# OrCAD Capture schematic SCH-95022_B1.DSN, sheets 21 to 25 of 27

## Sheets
21 Page27 WIFI/BT: size B
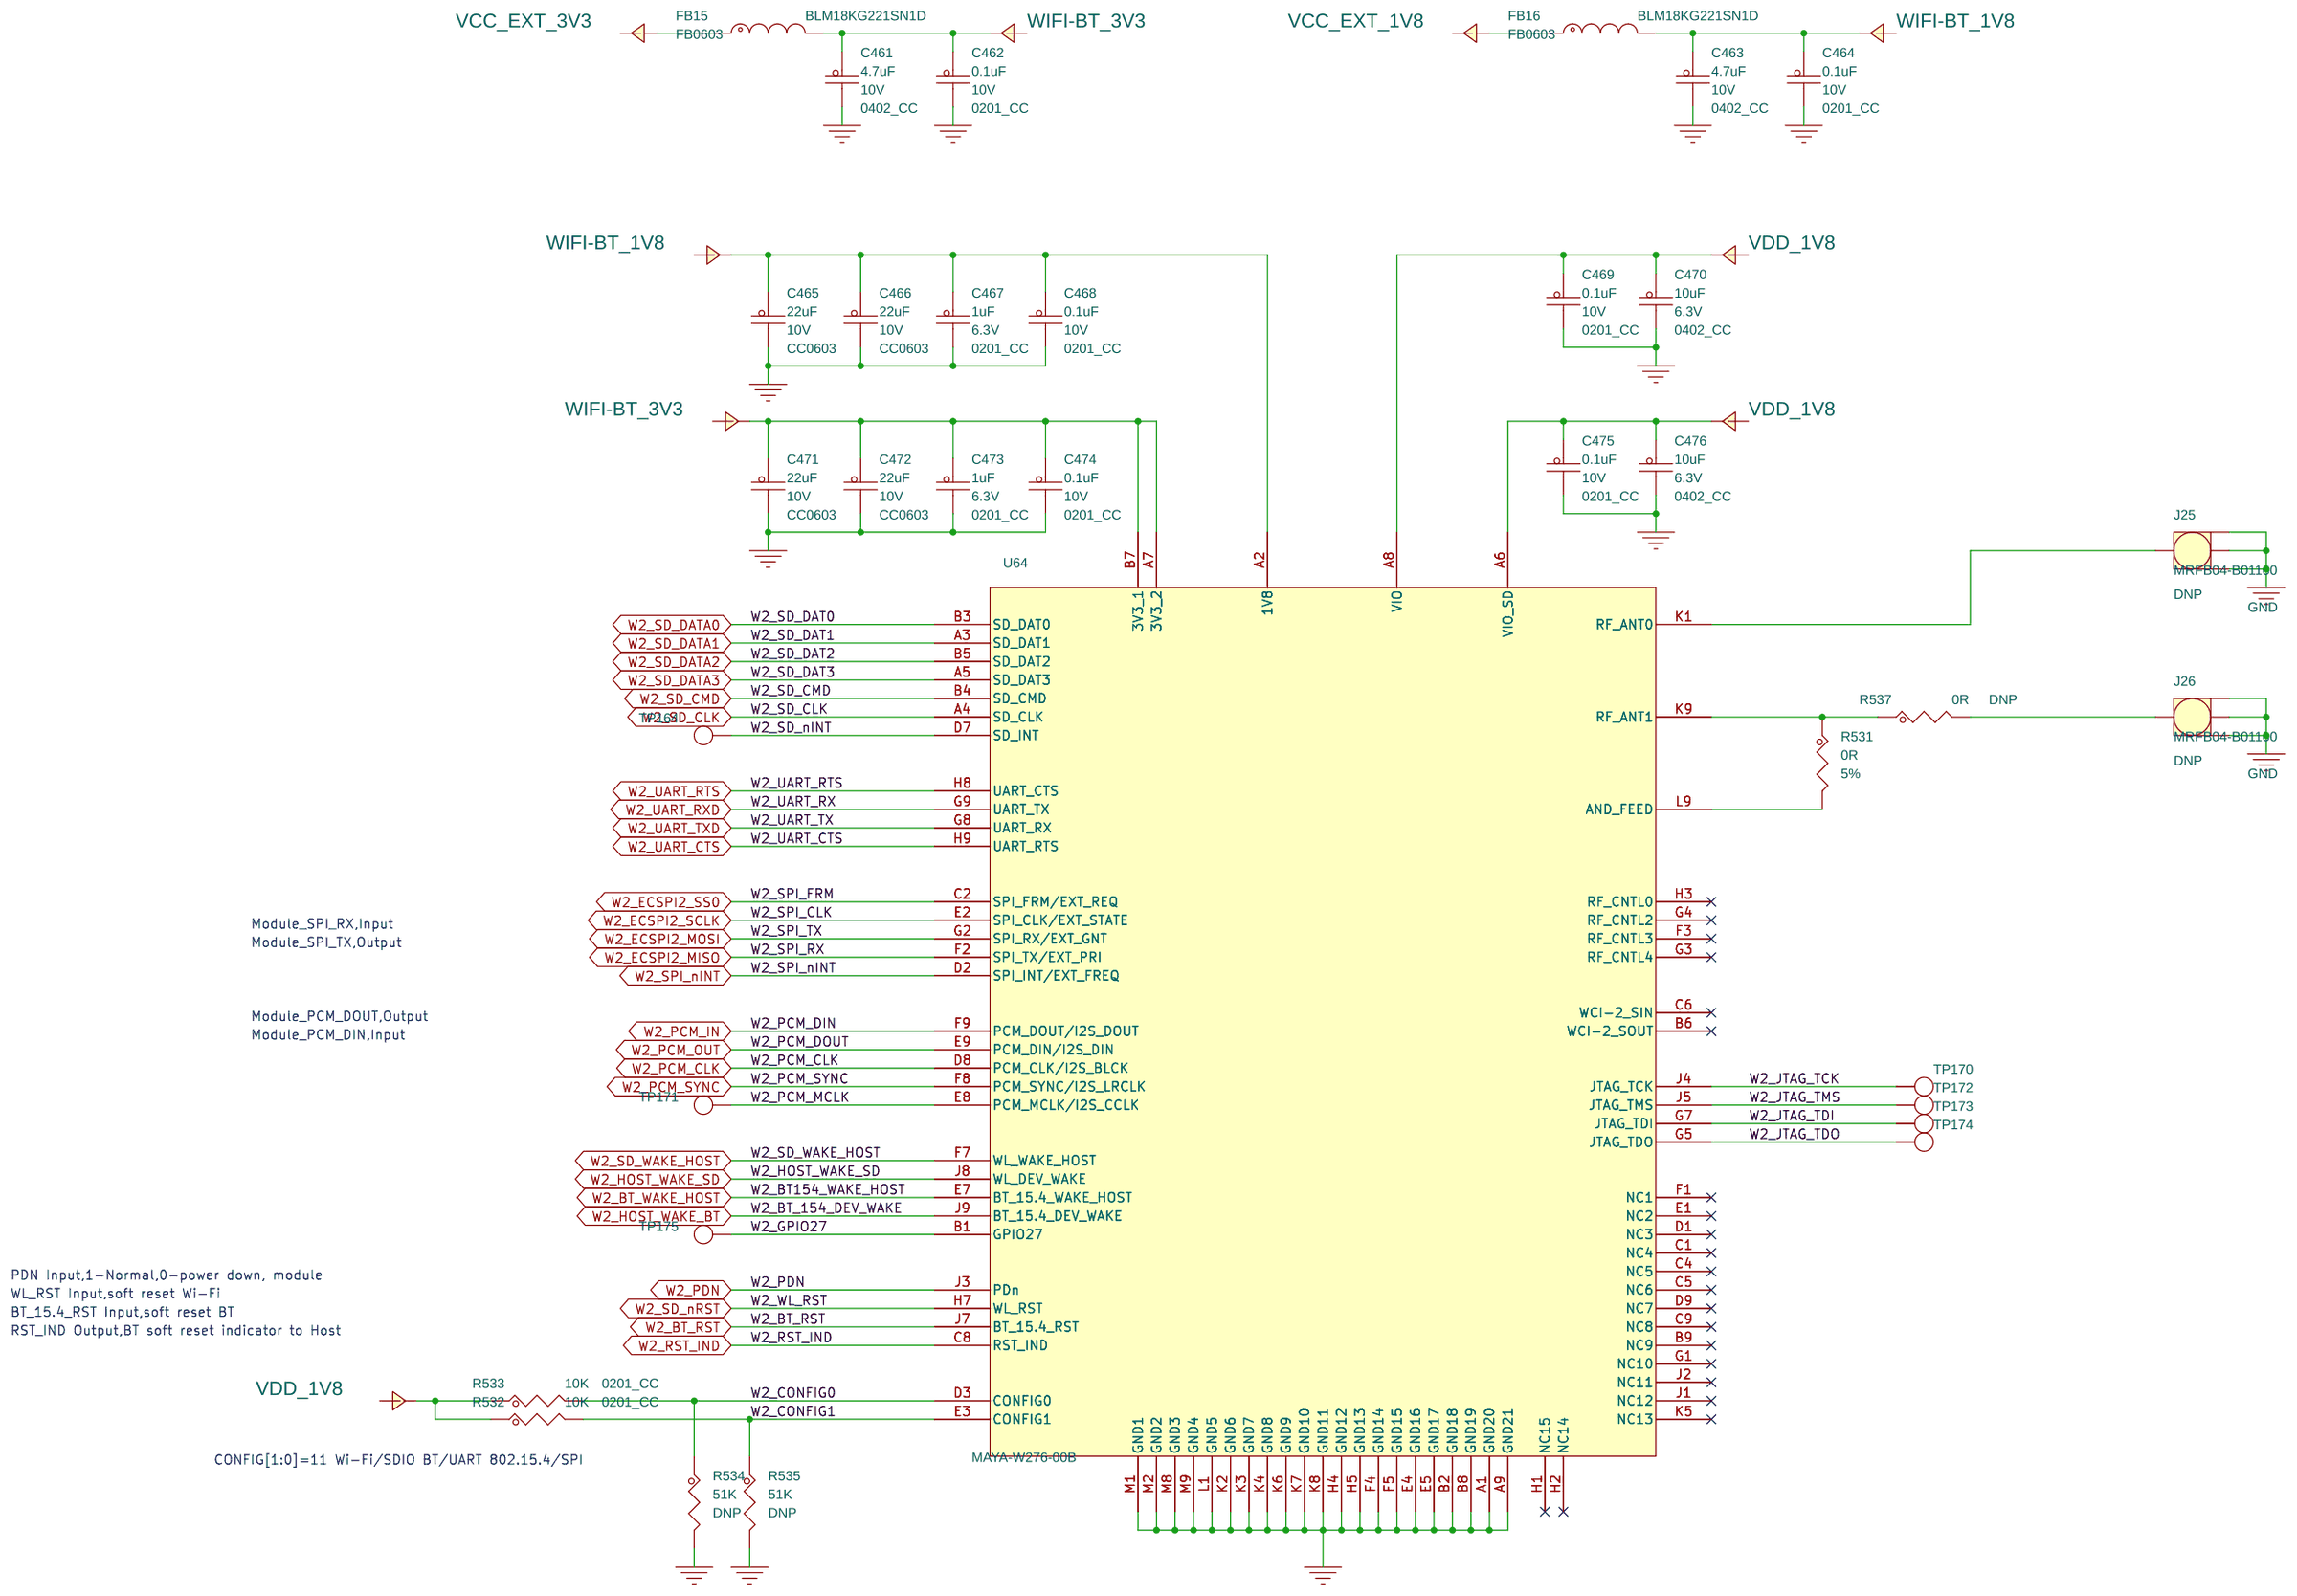
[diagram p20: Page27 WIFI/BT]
22 Page09 eMMC/QSPI: size B
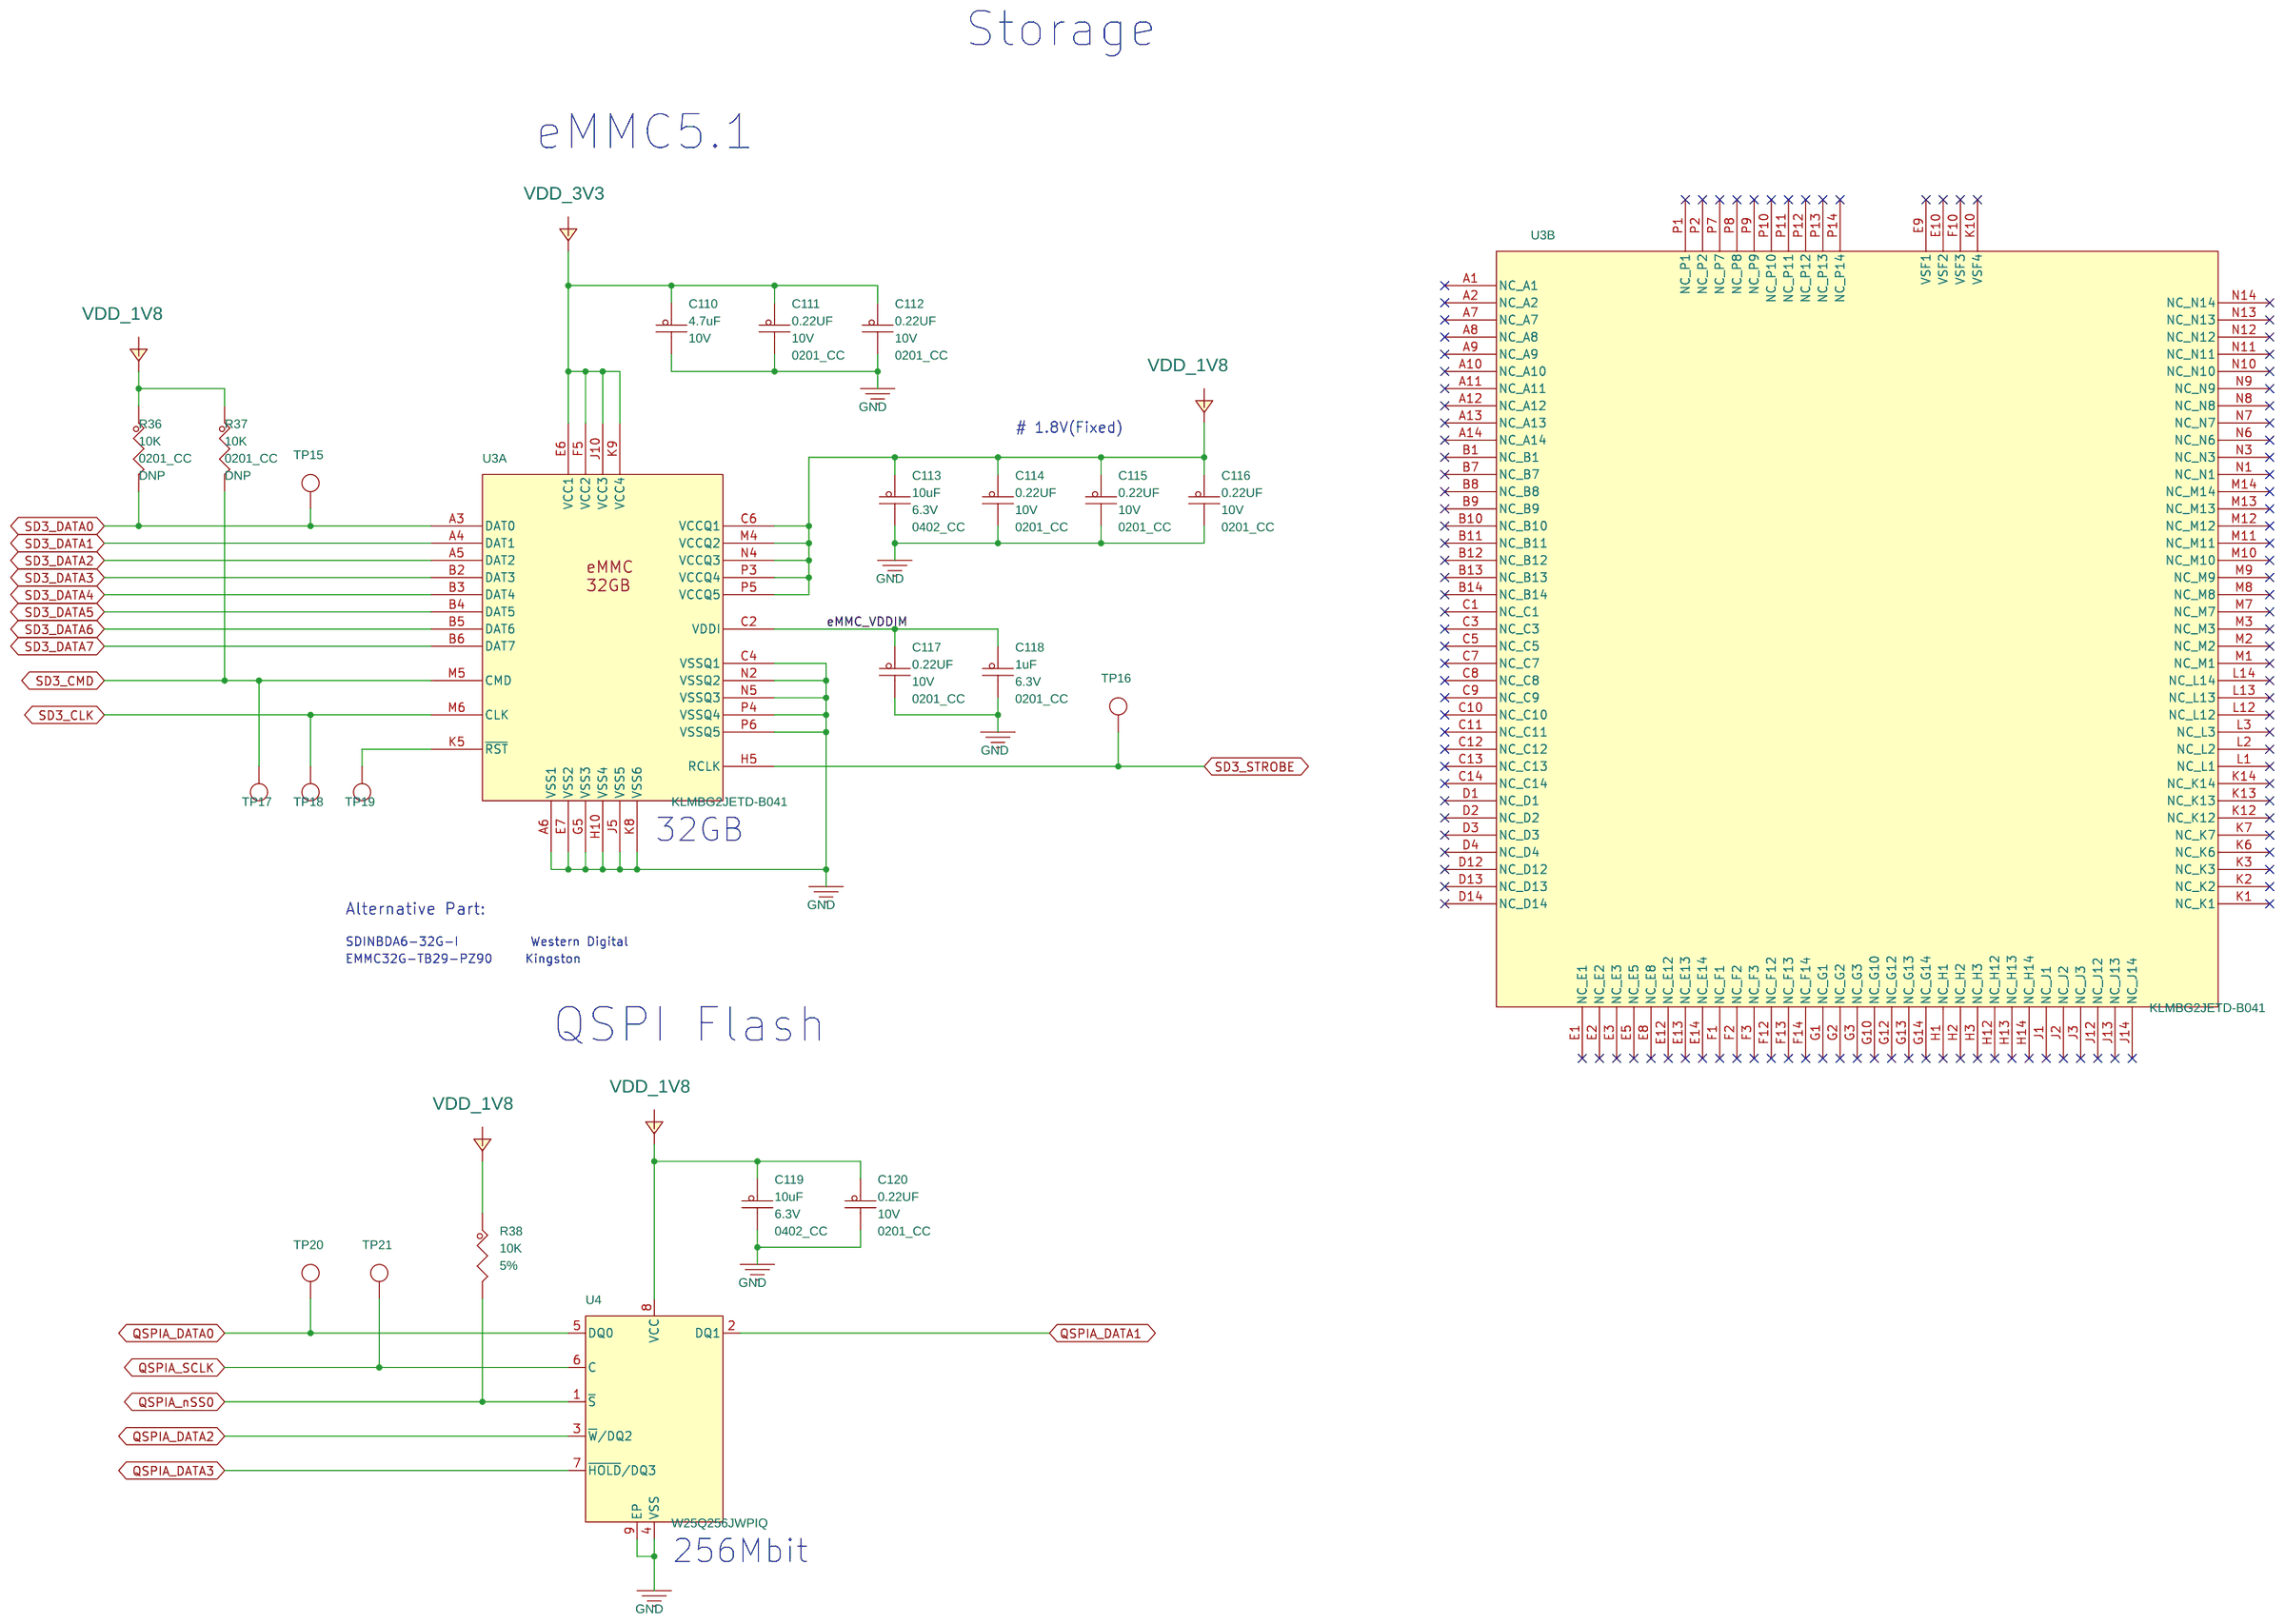
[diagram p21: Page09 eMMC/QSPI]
23 Page26 M.2 KEY-E WIFI/BT: size A3
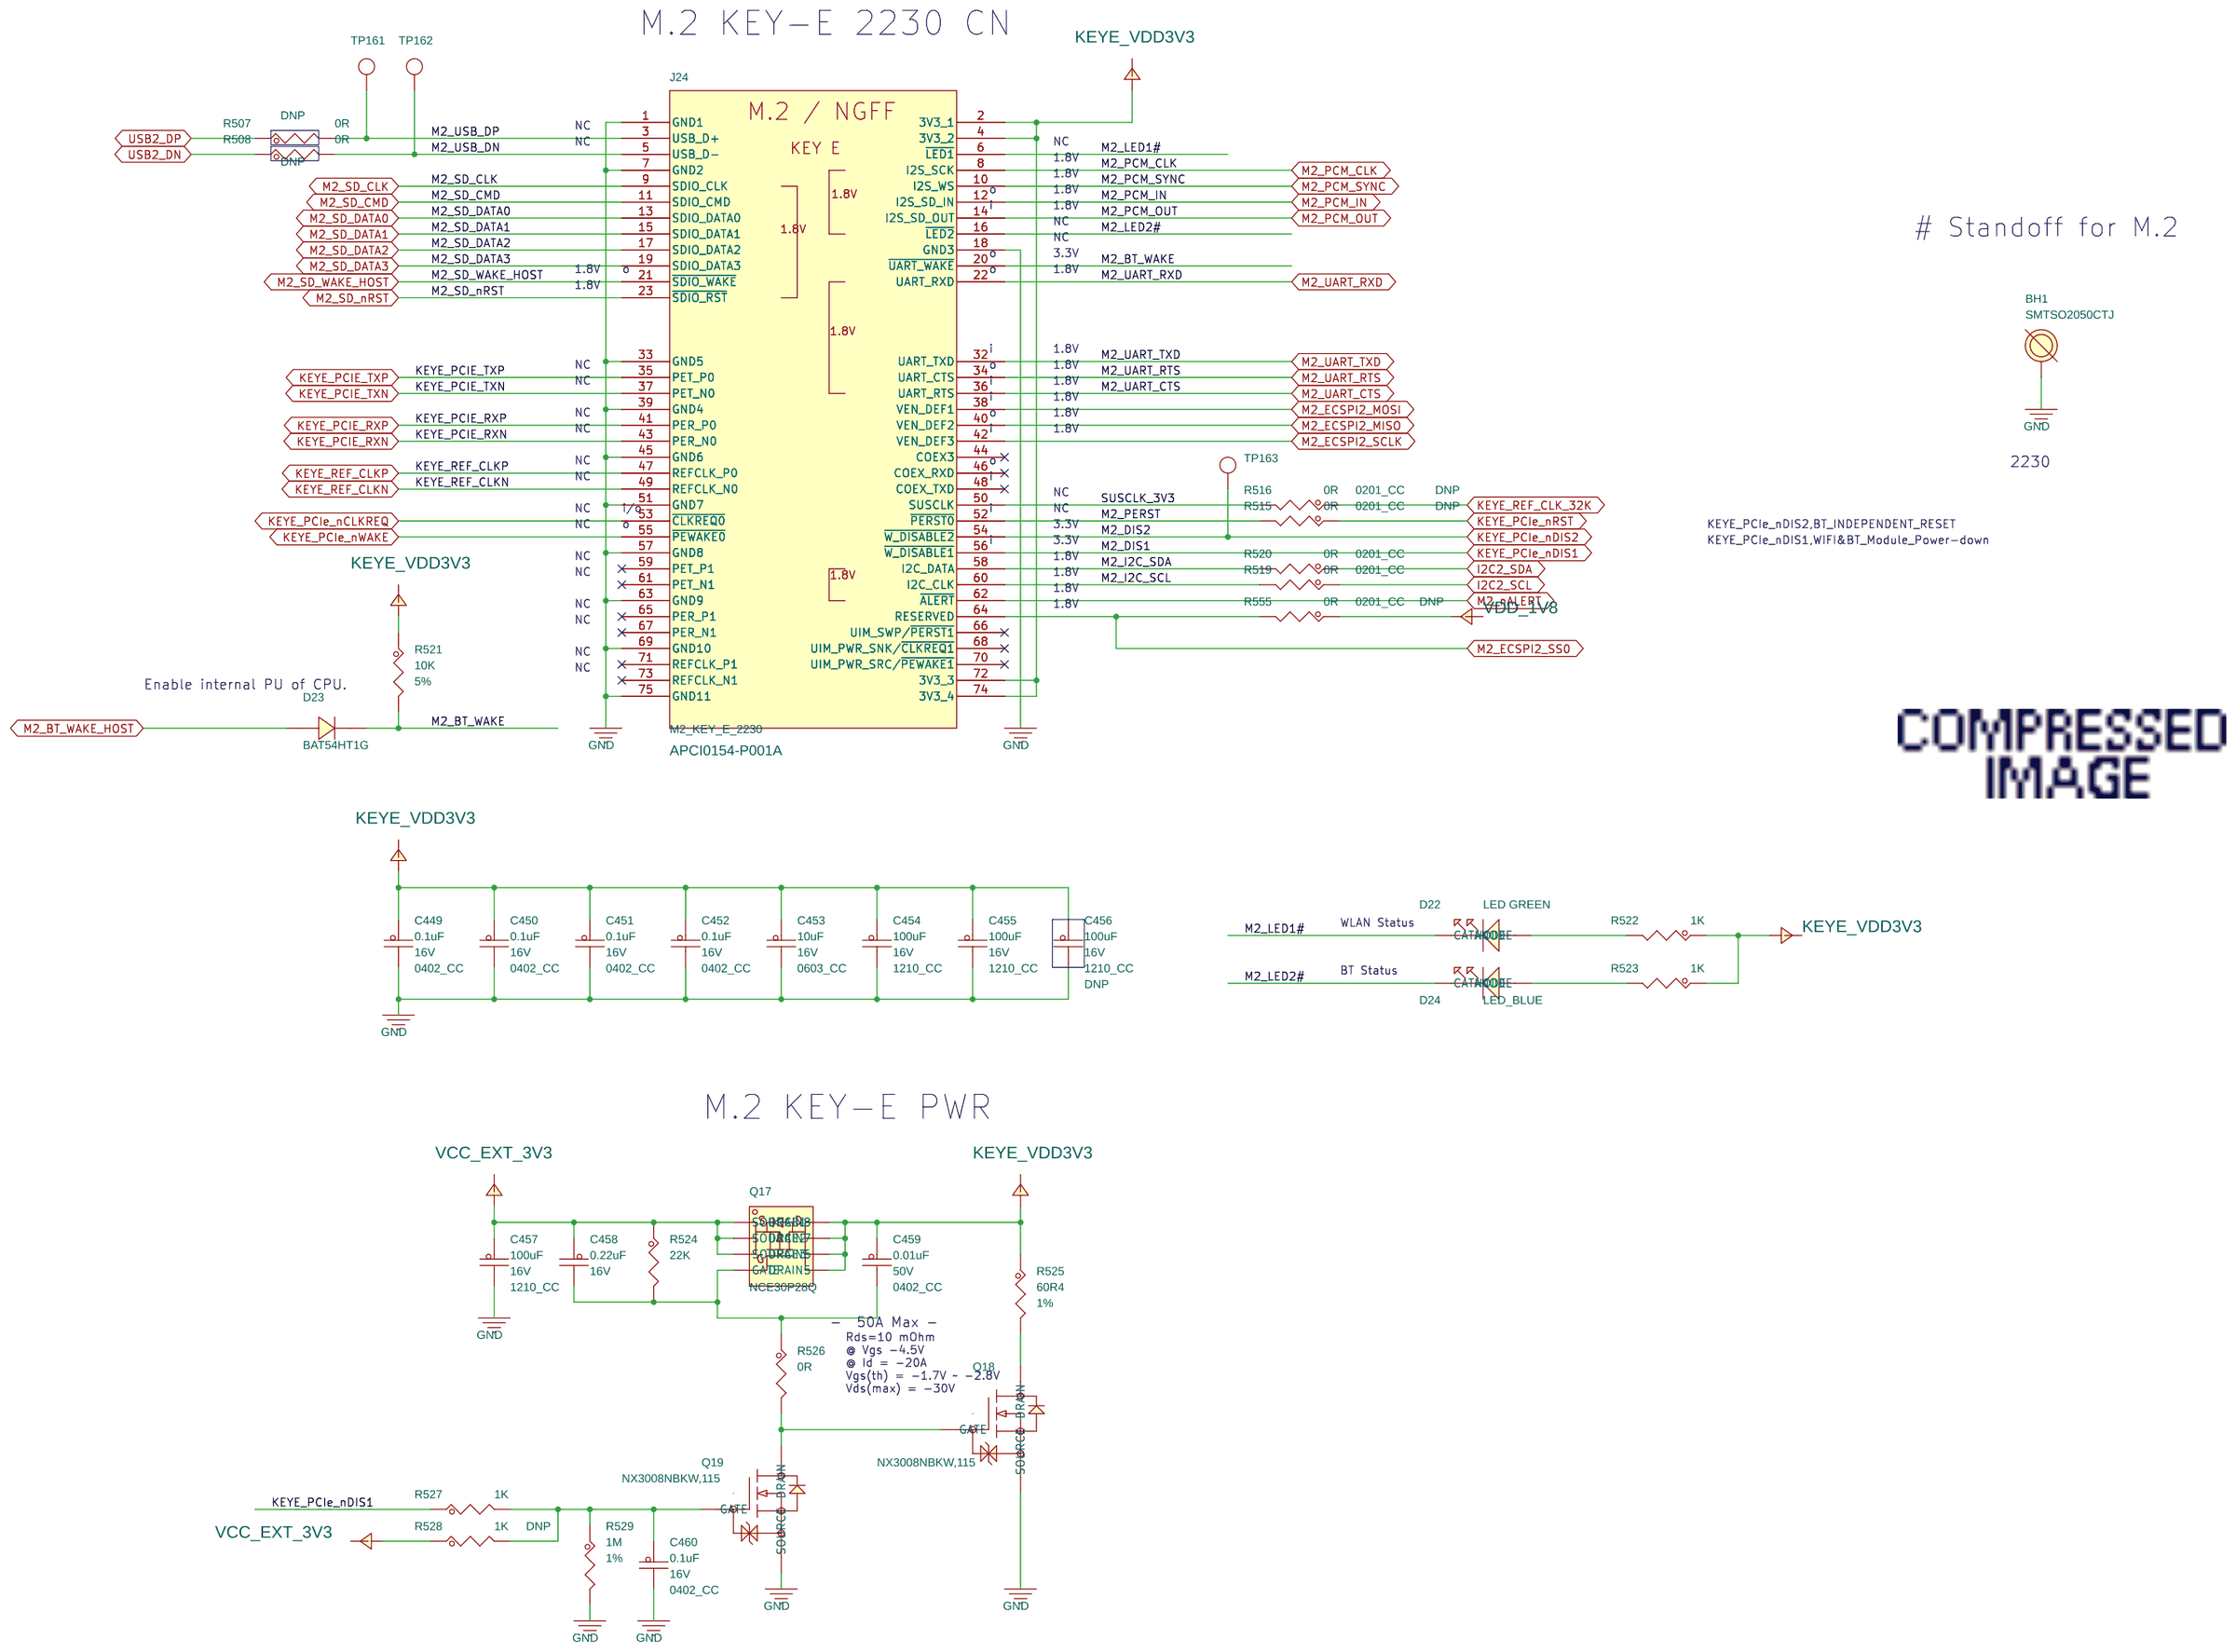
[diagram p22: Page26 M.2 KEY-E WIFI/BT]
24 Page22 DEBUG/JTAG/CAN/RTC: size C
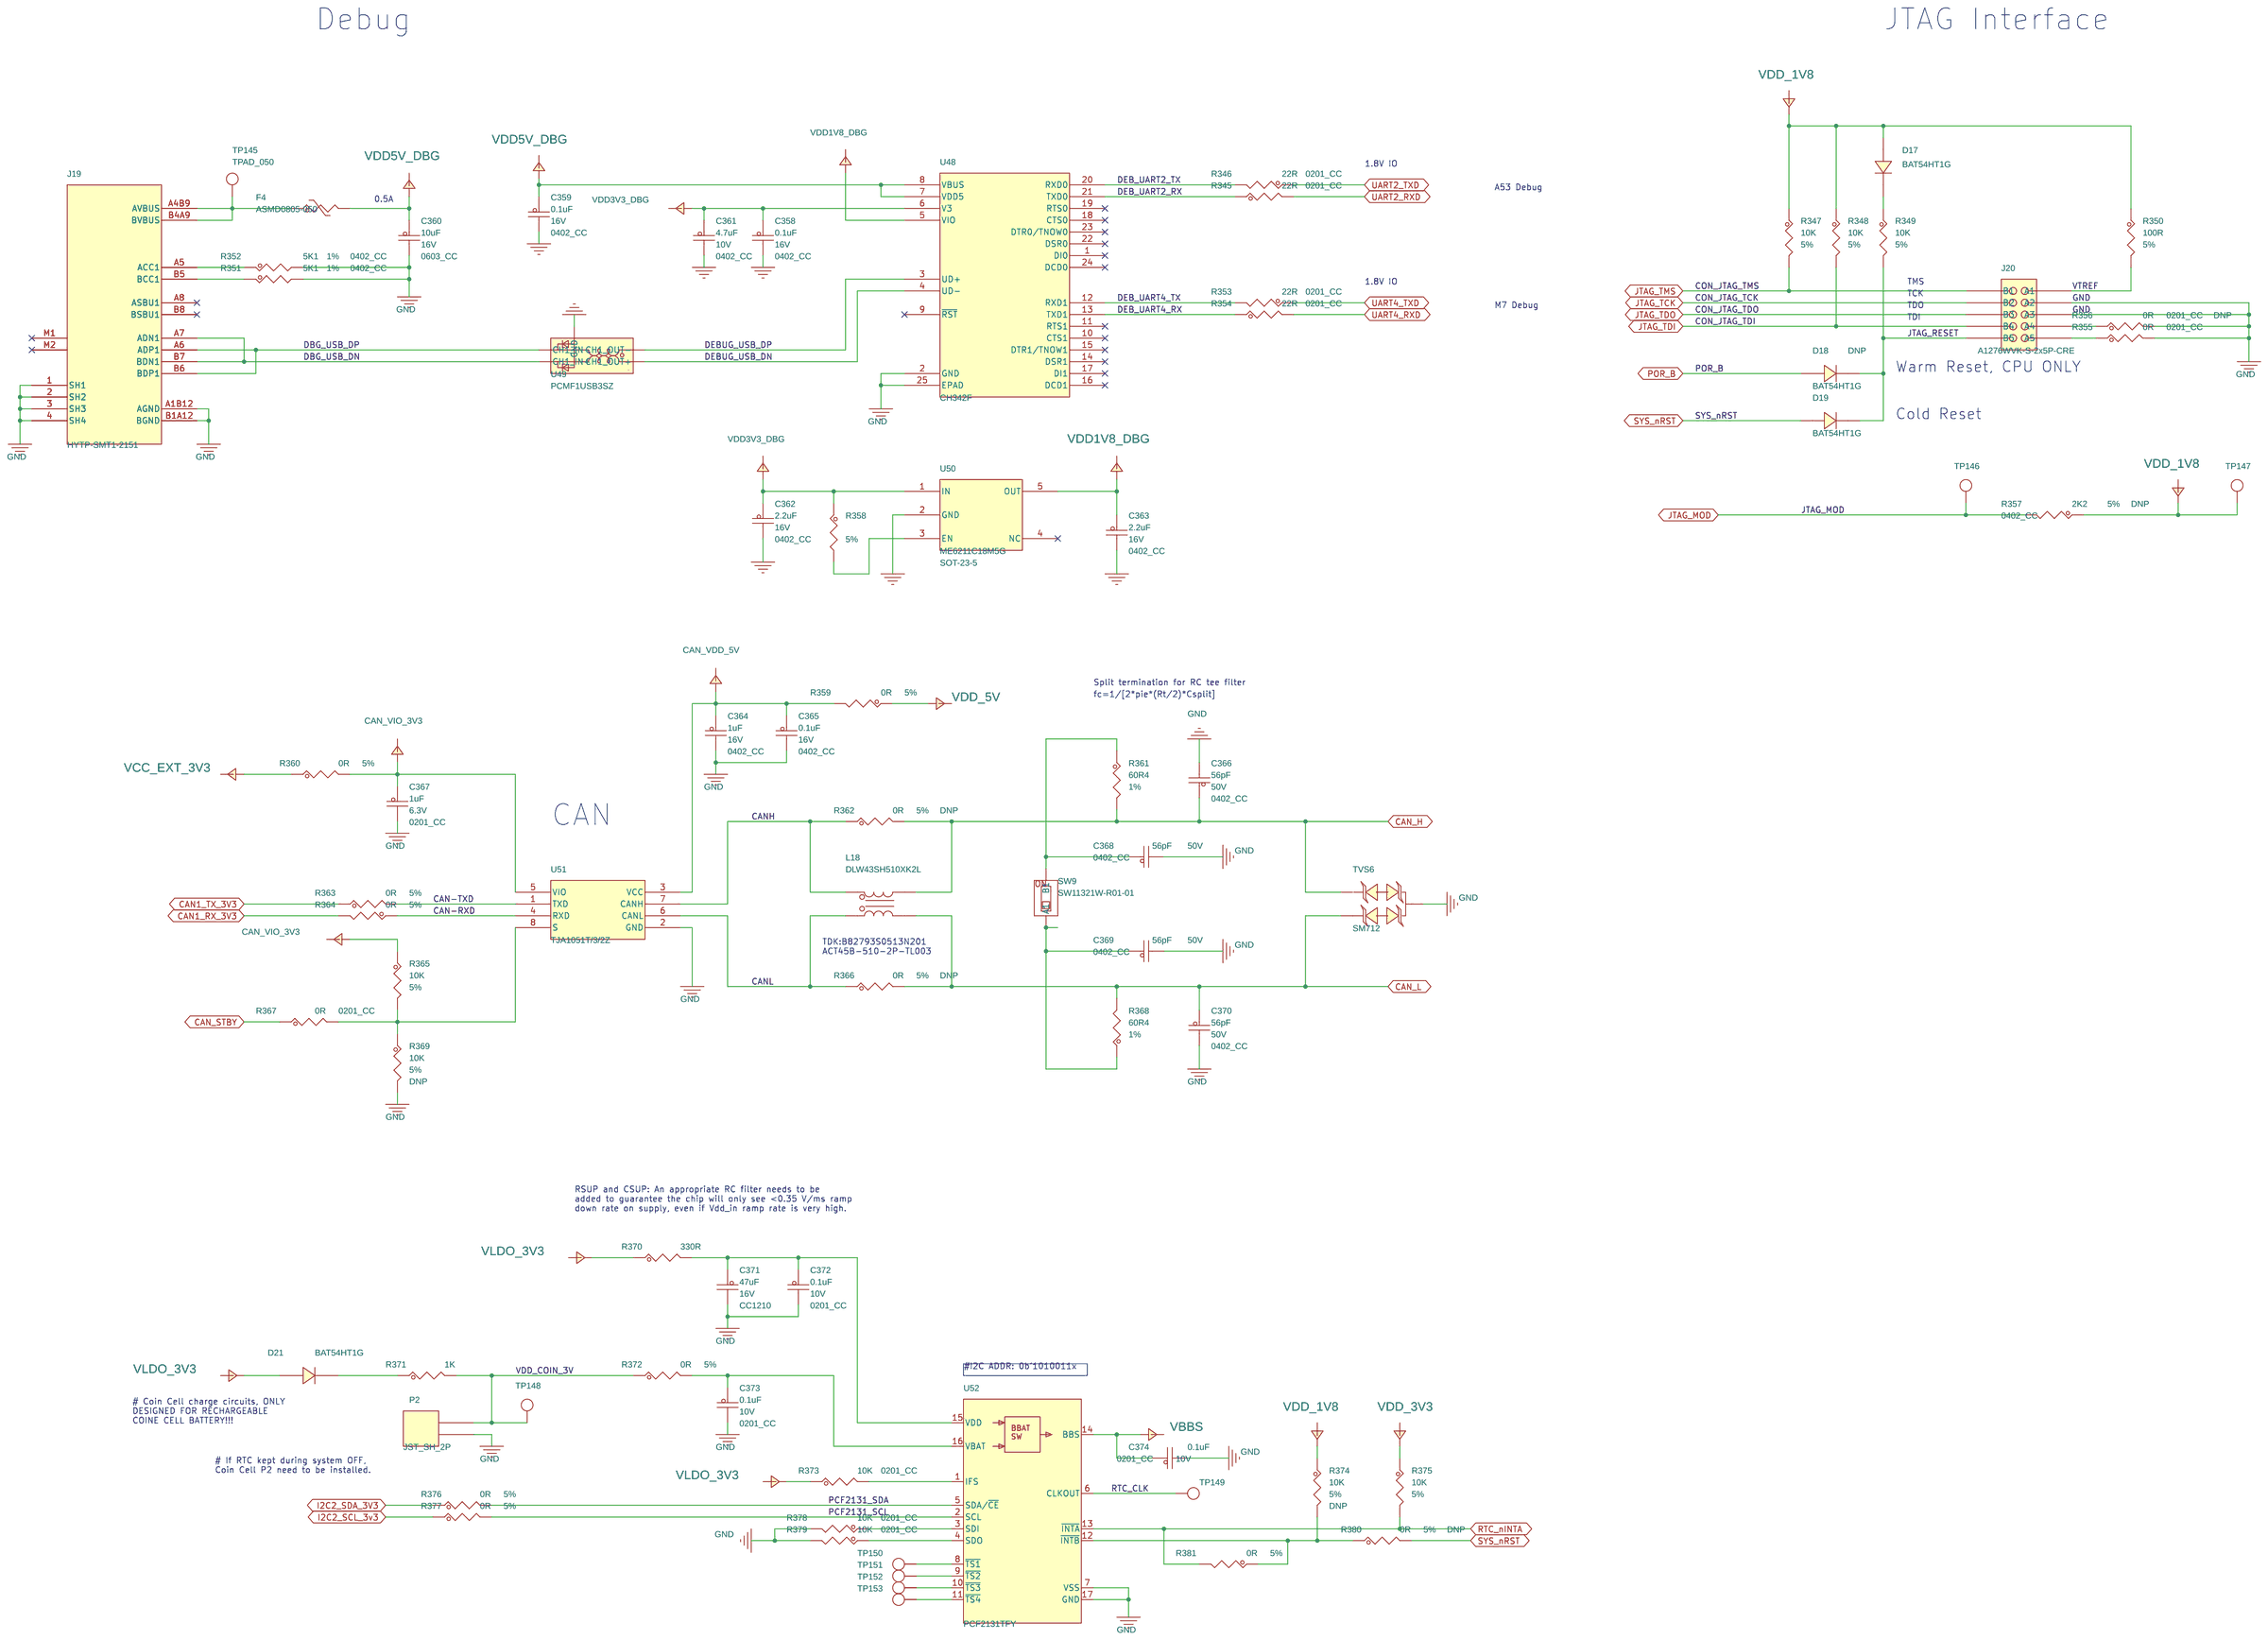
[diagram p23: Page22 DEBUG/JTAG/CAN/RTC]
25 Page19 MIPI CSI1/CSI2/DSI: size B
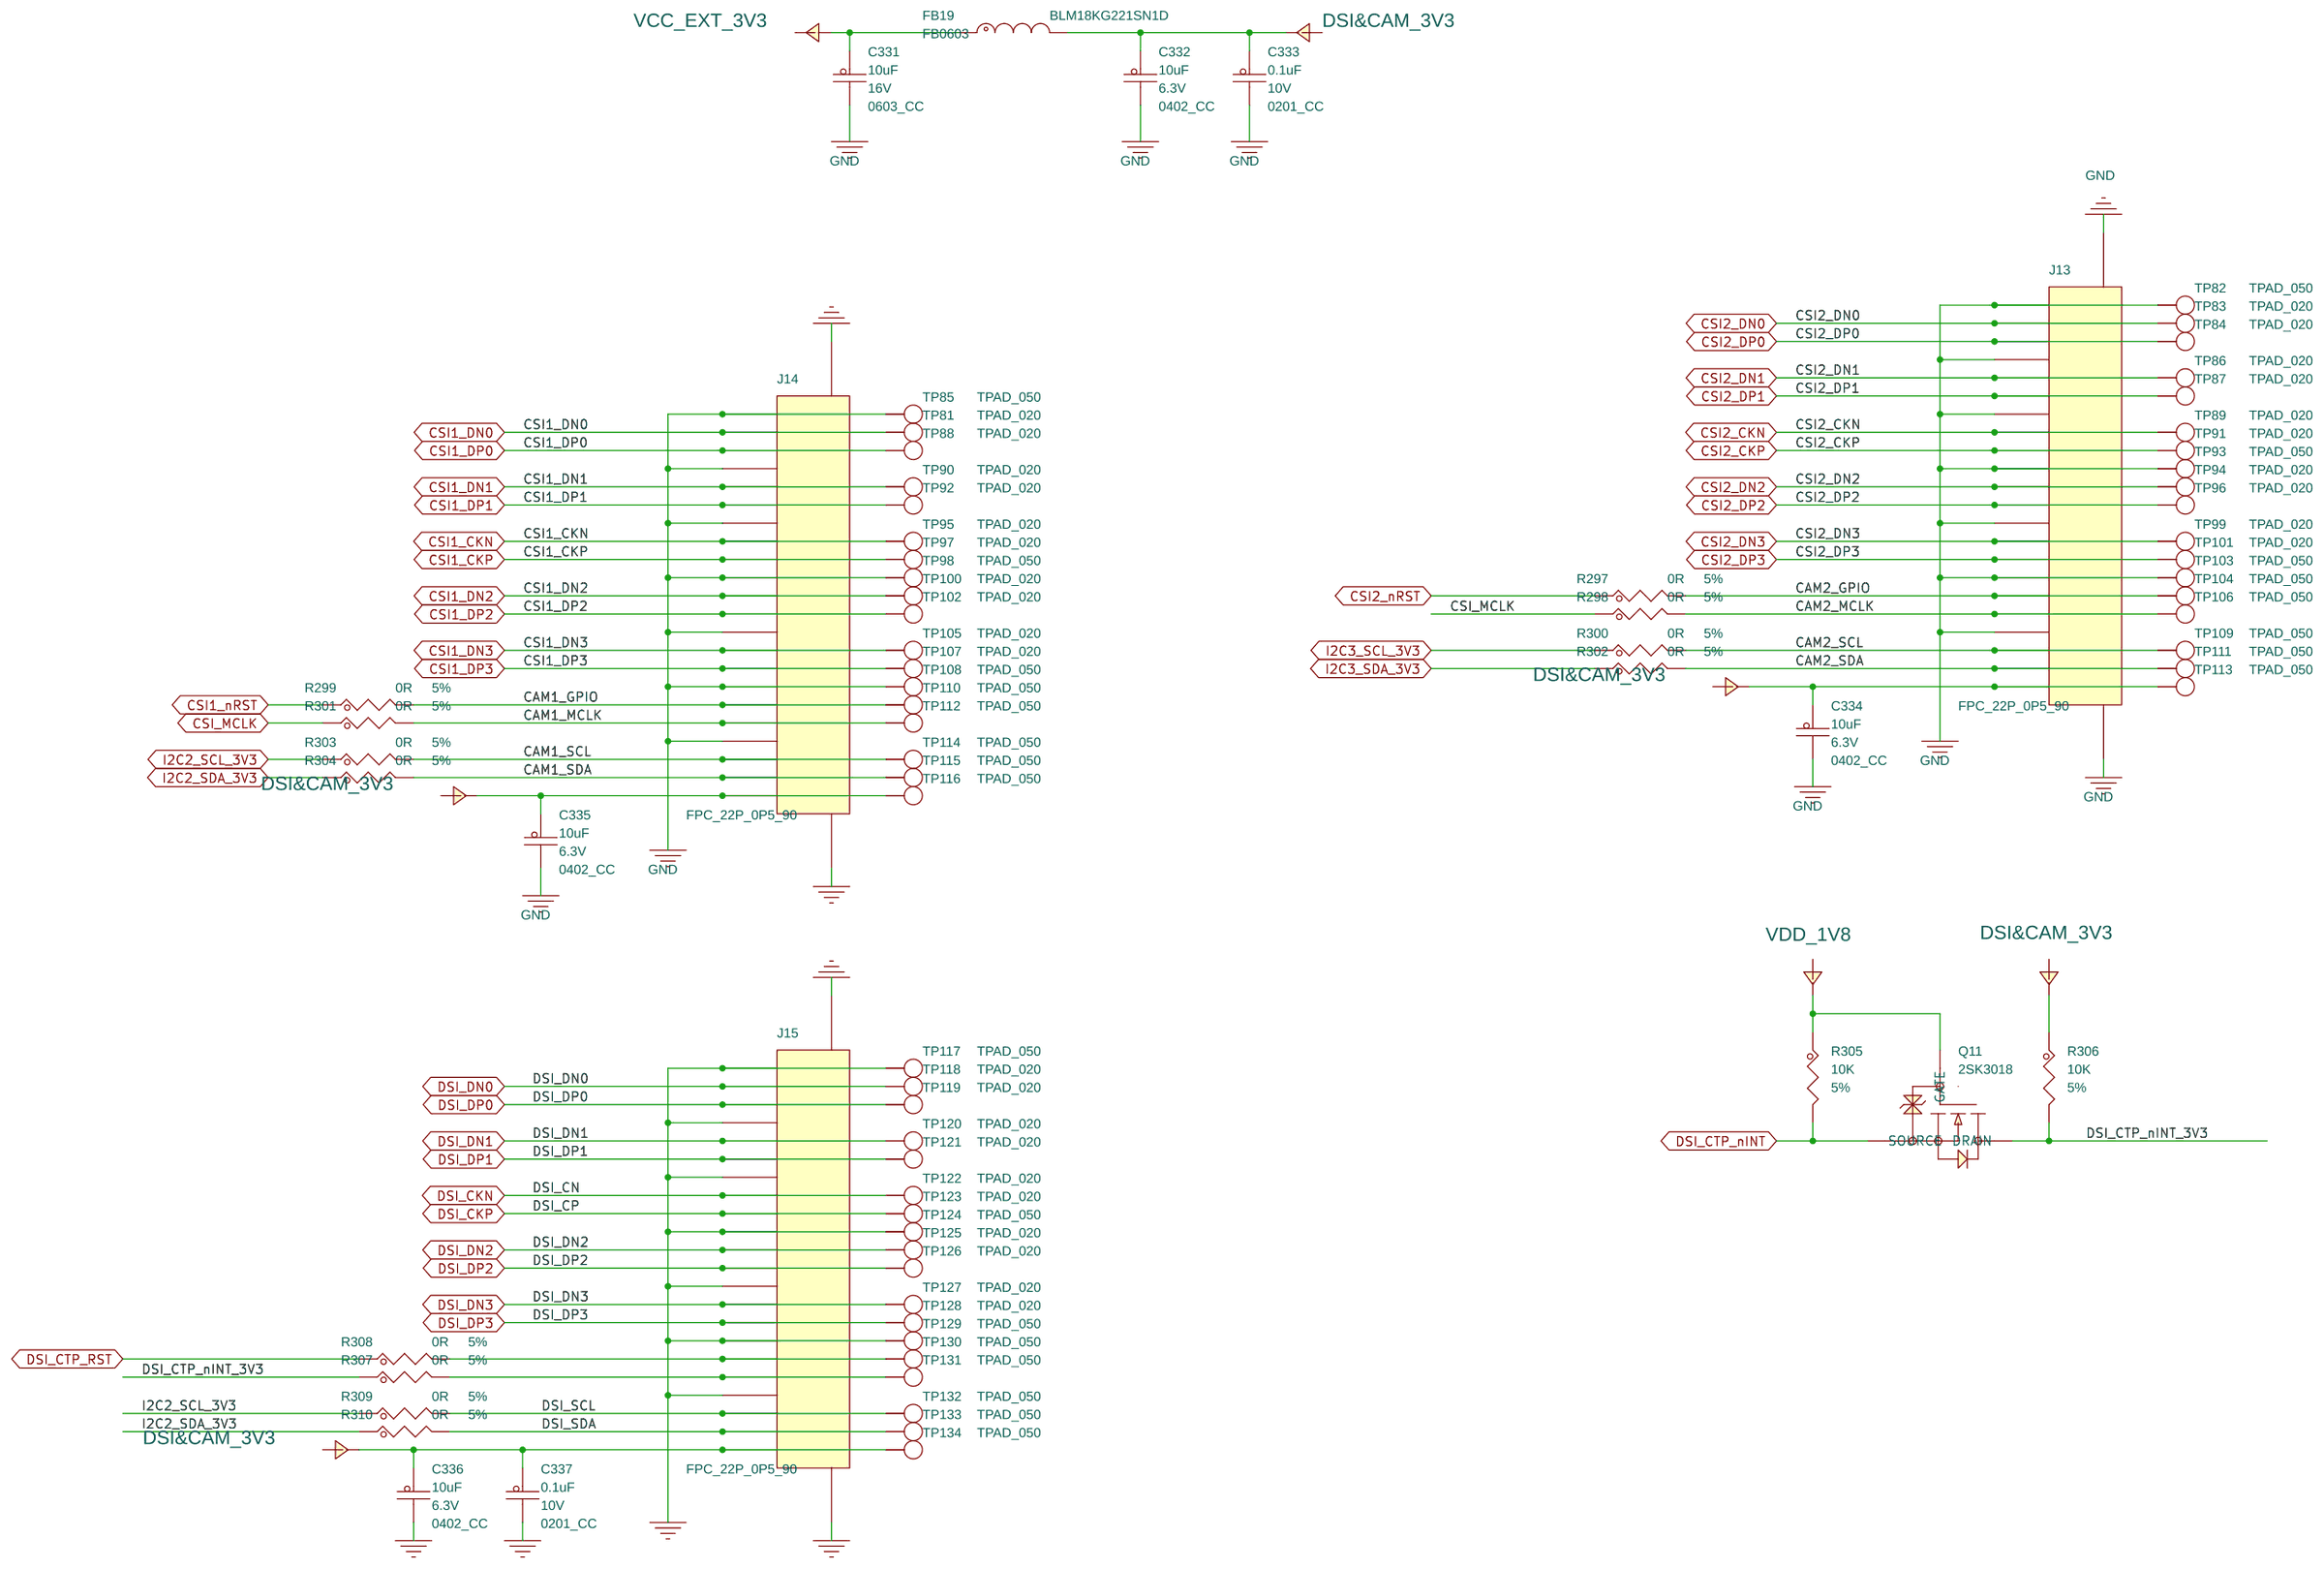
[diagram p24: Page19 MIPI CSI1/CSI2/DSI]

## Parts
sheet Page09 eMMC/QSPI
C110  4.7uF  [0402_CC]
C111  0.22UF  [0201_CC]
C112  0.22UF  [0201_CC]
C113  10uF  [0402_CC]
C114  0.22UF  [0201_CC]
C115  0.22UF  [0201_CC]
C116  0.22UF  [0201_CC]
C117  0.22UF  [0201_CC]
C118  1uF  [0201_CC]
C119  10uF  [0402_CC]
C120  0.22UF  [0201_CC]
R36  10K  [0201_CC]
R37  10K  [0201_CC]
R38  10K  [0402_CC]
TP15  TPAD_020  [tpad_020]
TP16  TPAD_020  [tpad_020]
TP17  TPAD_020  [tpad_020]
TP18  TPAD_020  [tpad_020]
TP19  TPAD_015  [TPAD_015]
TP20  TPAD_015  [TPAD_015]
TP21  TPAD_015  [TPAD_015]
U3  KLMBG2JETD-B041  [fbga153_0p5_11p5x13]  (sections A,B)
U4  W25Q256JWPIQ  [dfn8_1p27_6x5mm_3p1]
sheet Page19 MIPI CSI1/CSI2/DSI
C331  10uF  [0603_CC]
C332  10uF  [0402_CC]
C333  0.1uF  [0201_CC]
C334  10uF  [0402_CC]
C335  10uF  [0402_CC]
C336  10uF  [0402_CC]
C337  0.1uF  [0201_CC]
FB19  BLM18KG221SN1D  [FB0603]
J13  FPC_22P_0P5_90  [FPC_22P_0P5_90]
J14  FPC_22P_0P5_90  [FPC_22P_0P5_90]
J15  FPC_22P_0P5_90  [FPC_22P_0P5_90]
Q11  2SK3018  [SOT_323]
R297  0R  [0402_CC]
R298  0R  [0402_CC]
R299  0R  [0402_CC]
R300  0R  [0402_CC]
R301  0R  [0402_CC]
R302  0R  [0402_CC]
R303  0R  [0402_CC]
R304  0R  [0402_CC]
R305  10K  [0402_CC]
R306  10K  [0402_CC]
R307  0R  [0402_CC]
R308  0R  [0402_CC]
R309  0R  [0402_CC]
R310  0R  [0402_CC]
TP81  TPAD_020  [TPAD_020]
TP82  TPAD_050  [TPAD_050]
TP83  TPAD_020  [TPAD_020]
TP84  TPAD_020  [TPAD_020]
TP85  TPAD_050  [TPAD_050]
TP86  TPAD_020  [TPAD_020]
TP87  TPAD_020  [TPAD_020]
TP88  TPAD_020  [TPAD_020]
TP89  TPAD_020  [TPAD_020]
TP90  TPAD_020  [TPAD_020]
TP91  TPAD_020  [TPAD_020]
TP92  TPAD_020  [TPAD_020]
TP93  TPAD_050  [TPAD_050]
TP94  TPAD_020  [TPAD_020]
TP95  TPAD_020  [TPAD_020]
TP96  TPAD_020  [TPAD_020]
TP97  TPAD_020  [TPAD_020]
TP98  TPAD_050  [TPAD_050]
TP99  TPAD_020  [TPAD_020]
TP100  TPAD_020  [TPAD_020]
TP101  TPAD_020  [TPAD_020]
TP102  TPAD_020  [TPAD_020]
TP103  TPAD_050  [TPAD_050]
TP104  TPAD_050  [TPAD_050]
TP105  TPAD_020  [TPAD_020]
TP106  TPAD_050  [TPAD_050]
TP107  TPAD_020  [TPAD_020]
TP108  TPAD_050  [TPAD_050]
TP109  TPAD_050  [TPAD_050]
TP110  TPAD_050  [TPAD_050]
TP111  TPAD_050  [TPAD_050]
TP112  TPAD_050  [TPAD_050]
TP113  TPAD_050  [TPAD_050]
TP114  TPAD_050  [TPAD_050]
TP115  TPAD_050  [TPAD_050]
TP116  TPAD_050  [TPAD_050]
TP117  TPAD_050  [TPAD_050]
TP118  TPAD_020  [TPAD_020]
TP119  TPAD_020  [TPAD_020]
TP120  TPAD_020  [TPAD_020]
TP121  TPAD_020  [TPAD_020]
TP122  TPAD_020  [TPAD_020]
TP123  TPAD_020  [TPAD_020]
TP124  TPAD_050  [TPAD_050]
TP125  TPAD_020  [TPAD_020]
TP126  TPAD_020  [TPAD_020]
TP127  TPAD_020  [TPAD_020]
TP128  TPAD_020  [TPAD_020]
TP129  TPAD_050  [TPAD_050]
TP130  TPAD_050  [TPAD_050]
TP131  TPAD_050  [TPAD_050]
TP132  TPAD_050  [TPAD_050]
TP133  TPAD_050  [TPAD_050]
TP134  TPAD_050  [TPAD_050]
sheet Page22 DEBUG/JTAG/CAN/RTC
C358  0.1uF  [0402_CC]
C359  0.1uF  [0402_CC]
C360  10uF  [0603_CC]
C361  4.7uF  [0402_CC]
C362  2.2uF  [0402_CC]
C363  2.2uF  [0402_CC]
C364  1uF  [0402_CC]
C365  0.1uF  [0402_CC]
C366  56pF  [0402_CC]
C367  1uF  [0201_CC]
C368  56pF  [0402_CC]
C369  56pF  [0402_CC]
C370  56pF  [0402_CC]
C371  47uF  [CC1210]
C372  0.1uF  [0201_CC]
C373  0.1uF  [0201_CC]
C374  0.1uF  [0201_CC]
D17  BAT54HT1G  [SOD323]
D18  BAT54HT1G  [SOD323]
D19  BAT54HT1G  [SOD323]
D21  BAT54HT1G  [SOD323]
F4  ASMD0805-050  [R0805]
J19  HYTP-SMT1-2151  [TYPEC16P_8P94X7P30X3P16]
J20  A1276WVK-S-2x5P-CRE  [hdr205_10m_50_sm_k]
L18  DLW43SH510XK2L  [IND_DLW43]
P2  JST_SH_2P  [sh_2p]
R345  22R  [0201_CC]
R346  22R  [0201_CC]
R347  10K  [0402_CC]
R348  10K  [0402_CC]
R349  10K  [0402_CC]
R350  100R  [0402_CC]
R351  5K1  [0402_CC]
R352  5K1  [0402_CC]
R353  22R  [0201_CC]
R354  22R  [0201_CC]
R355  0R  [0201_CC]
R356  0R  [0201_CC]
R357  2K2  [0402_CC]
R358  100K  [0402_CC]
R359  0R  [0402_CC]
R360  0R  [0402_CC]
R361  60R4  [0603_CC]
R362  0R  [0402_CC]
R363  0R  [0402_CC]
R364  0R  [0402_CC]
R365  10K  [0402_CC]
R366  0R  [0402_CC]
R367  0R  [0201_CC]
R368  60R4  [0603_CC]
R369  10K  [0402_CC]
R370  330R  [0402_CC]
R371  1K  [0402_CC]
R372  0R  [0402_CC]
R373  10K  [0201_CC]
R374  10K  [0402_CC]
R375  10K  [0402_CC]
R376  0R  [0402_CC]
R377  0R  [0402_CC]
R378  10K  [0201_CC]
R379  10K  [0201_CC]
R380  0R  [0402_CC]
R381  0R  [0402_CC]
SW9  SW11321W-R01-01  [SW_1P27_1P]
TP145  TPAD_050  [TPAD_050]
TP146  TPAD_050  [TPAD_050]
TP147  TPAD_050  [TPAD_050]
TP148  TPAD_020  [tpad_020]
TP149  TPAD_015  [TPAD_015]
TP150  TPAD_015  [TPAD_015]
TP151  TPAD_015  [TPAD_015]
TP152  TPAD_015  [TPAD_015]
TP153  TPAD_015  [TPAD_015]
TVS6  SM712  [SOT-23]
U48  CH342F  [QFN24P_0_5]
U49  PCMF1USB3SZ  [wlcsp5_0p4_0p82x1p22]
U50  ME6211C18M5G  [SOT-23-5]
U51  TJA1051T/3/2Z  [SOP8]
U52  PCF2131TFY  [so16_0p5_3p5x4p5_mm]
sheet Page26 M.2 KEY-E WIFI/BT
BH1  SMTSO2050CTJ  [PTH_3R73x6R20]
C449  0.1uF  [0402_CC]
C450  0.1uF  [0402_CC]
C451  0.1uF  [0402_CC]
C452  0.1uF  [0402_CC]
C453  10uF  [0603_CC]
C454  100uF  [1210_CC]
C455  100uF  [1210_CC]
C456  100uF  [1210_CC]
C457  100uF  [1210_CC]
C458  0.22uF  [0402_CC]
C459  0.01uF  [0402_CC]
C460  0.1uF  [0402_CC]
D22  LED GREEN  [LED_0603]
D23  BAT54HT1G  [SOD323]
D24  LED_BLUE  [led_0603_11mil]
J24  M2_KEY_E_2230  [con_75_0p5_22x9_ra1]
Q17  NCE30P28Q  [DFN_3x3-8L]
Q18  NX3008NBKW,115  [sc70_3]
Q19  NX3008NBKW,115  [sc70_3]
R507  0R  [0402_CC]
R508  0R  [0402_CC]
R515  0R  [0201_CC]
R516  0R  [0201_CC]
R519  0R  [0201_CC]
R520  0R  [0201_CC]
R521  10K  [0402_CC]
R522  1K  [0402_CC]
R523  1K  [0402_CC]
R524  22K  [0402_CC]
R525  60R4  [0603_CC]
R526  0R  [0402_CC]
R527  1K  [0402_CC]
R528  1K  [0402_CC]
R529  1M  [0402_CC]
R555  0R  [0201_CC]
TP161  TPAD_020  [tpad_020]
TP162  TPAD_020  [tpad_020]
TP163  TPAD_020  [tpad_020]
sheet Page27 WIFI/BT
C461  4.7uF  [0402_CC]
C462  0.1uF  [0201_CC]
C463  4.7uF  [0402_CC]
C464  0.1uF  [0201_CC]
C465  22uF  [CC0603]
C466  22uF  [CC0603]
C467  1uF  [0201_CC]
C468  0.1uF  [0201_CC]
C469  0.1uF  [0201_CC]
C470  10uF  [0402_CC]
C471  22uF  [CC0603]
C472  22uF  [CC0603]
C473  1uF  [0201_CC]
C474  0.1uF  [0201_CC]
C475  0.1uF  [0201_CC]
C476  10uF  [0402_CC]
FB15  BLM18KG221SN1D  [FB0603]
FB16  BLM18KG221SN1D  [FB0603]
J25  MRFB04-B01100  [IPEX_4]
J26  MRFB04-B01100  [IPEX_4]
R531  0R  [0402_CC]
R532  10K  [0201_CC]
R533  10K  [0201_CC]
R534  51K  [0402_CC]
R535  51K  [0402_CC]
R537  0R  [0402_CC]
TP164  TPAD_015  [TPAD_015]
TP170  TPAD_015  [TPAD_015]
TP171  TPAD_015  [TPAD_015]
TP172  TPAD_015  [TPAD_015]
TP173  TPAD_015  [TPAD_015]
TP174  TPAD_015  [TPAD_015]
TP175  TPAD_015  [TPAD_015]
U64  MAYA-W276-00B  [MAYA-W2]

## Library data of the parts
C110 C361 C461 C463 = CAP_NP: CAP CER 4.7uF 10V 10% X5R 0402; CAD_APPROVED: Yes; HEIGHT: 0.95MM; MFG_NAME01: SAMSUNG; MFG_PN01: CL05A475KP5NRNC; Polyhex_Number: PD.005.0058; ROHS: Yes; Temp Range: -55°C to + 85°C; Tolerance: 10%; VOLTAGE: 10V
C111 C112 C114-C117 C120 = CAP_NP: CAP CER 0.22UF 10V 20% X5R 0201; AGILE_PN: 150-78815; CAD_APPROVED: Yes; FPLIST: CC0201,CC0201_HD,0201_CC; HEIGHT: 0.33MM; MFG_NAME01: SAMSUNG; MFG_PN01: CL03A224KP3NNNH; Polyhex_Number: PD.005.0029; ROHS: Yes; Tolerance: 20%; VOLTAGE: 10V
C113 C119 C332 C334-C336 C470 C476 = CAP_NP: CAP CER 10UF 6.3V 20% X5R 0402; AGILE_PN: 150-79163; CAD_APPROVED: Yes; FPLIST: CC0402_25,CC0402_HD,0402_CC; HEIGHT: 0.65 MM; MFG_NAME01: SAMSUNG; MFG_PN01: CL05A106MQ5NUNC; Polyhex_Number: PD.005.0031; ROHS: Yes; Tolerance: 20%; VOLTAGE: 6.3V
C118 C367 C467 C473 = CAP_NP: CAP CER 1uF 6.3V 10% X5R 0201; AGILE_PN: 150-79407; CAD_APPROVED: Yes; FPLIST: CC0201,CC0201_HD,0201_CC,0201_CC_012SM_NSP; HEIGHT: 0.35MM; MFG_NAME01: SAMSUNG; MFG_PN01: CL03A105KQ3CSNH; Package Size: 0201; Package Type: 7” reel; Polyhex_Number: PD.005.0030; ROHS: Yes; Tolerance: 10%; VOLTAGE: 6.3V
R36 R37 = RES: RES MF 10K 1/20W 5% 0201; ASSY_OPT: DNP; CAD_APPROVED: Yes; HEIGHT: 0.23mm; MFG_NAME01: YAGEO; MFG_PN01: RC0201JR-0710KL; Polyhex_Number: PD.004.0069; ROHS: Yes; Tolerance: 5%; VOLTAGE: 25V
R38 R305 R306 R347-R349 R365 R375 R521 = RES: RES MF 10K 1/16W 5% 0402; AGILE_PN: 470-75557; CAD_APPROVED: Yes; FPLIST: RC0402_25,RC0402_HD,0402_CC; HEIGHT: 0.4 MM; MFG_NAME01: YAGEO; MFG_PN01: RC0402JR-0710KL; Polyhex_Number: PD.004.0010; ROHS: Yes; Tolerance: 5%; VOLTAGE: 50V
TP15-TP18 TP81 TP83 TP84 TP86-TP92 TP94-TP97 TP99-TP102 TP105 TP107 TP118-TP123 TP125-TP128 TP148 TP161-TP163 = TESTLOOP: TEST POINT PAD 0.5MM DIA SMT, NO PART TO ORDER; AGILE_PN: 211-77484; ASSY_OPT: DNP; CAD_APPROVED: Yes; HEIGHT: 0.1MM; MFG_NAME01: NOT A COMPONENT; MFG_PN01: NOT A COMPONENT; Polyhex_Number: TEST POINT; ROHS: Yes
TP19-TP21 TP149-TP153 TP164 TP170-TP175 = TestLoop: TEST POINT PAD 15MIL DIA SMT, NO PART TO ORDER; AGILE_PN: 211-76645; ASSY_OPT: DNP; CAD_APPROVED: Yes; HEIGHT: 0.1MM; MFG_NAME01: NOT A COMPONENT; MFG_PN01: NOT A COMPONENT; Polyhex_Number: TEST POINT; ROHS: Yes
U3 = SDINBDG4-16G_VFBGA_153P: IC MEM NAND FLASH 32GB eMMC 5.1 CTLR 2.7-3.6V FBGA153; AGILE_PN: 342-00840; HEIGHT: 1MM; MFG_NAME01: SAMSUNG; Package Size: 11.5 mm x 13 mm x 1 mm; Polyhex_Number: PD.008.0032; ROHS: YES; Supply Voltage: 2.7 V to 3.6 V; Temp Range: -25°C to +85°C; VOLTAGE: 2.7-3.6V
U4 = MT25QL256ABA1EW9_9P: IC MEM FLASH SERIAL NOR 256MBIT; AGILE_PN: 334-77688; CAD_APPROVED: Yes; HEIGHT: 0.8 MM; MFG_NAME01: WINDOND; Polyhex_Number: PD.008.0338; ROHS: Yes; VOLTAGE: 1.7-2V
C331 C360 C453 = CAP_NP: CAP CER 10uF 16V 10% X5R 0603; CAD_APPROVED: Yes; HEIGHT: 0.55 MM; MFG_NAME01: SAMSUNG; MFG_PN01: CL10A106MO8NQN; Package Size: 0603; Polyhex_Number: PD.005.0001; ROHS: Yes; Tolerance: 10%; VOLTAGE: 16V
C333 C337 C372-C374 C462 C464 C468 C469 C474 C475 = CAP_NP: CAP CER 0.1uF 10V 20% X5R 0201; CAD_APPROVED: Yes; HEIGHT: 0.35MM; MFG_NAME01: SAMSUNG; MFG_PN01: CL03A104KP3NNNC; Package Size: 0201; Package Type: 7” reel; Polyhex_Number: PD.005.0054; ROHS: Yes; Tolerance: 20%; VOLTAGE: 10V
FB15 FB16 FB19 = Ferrite_Bead: FERRITE 0603 220Ohm@100MHz 2A; HEIGHT: 0.5mm; Irms: <Irms>; MFG_NAME01: Murata; Polyhex_Number: PD.009.0001; Temp Range: -55C to +125C; Temp_Range: -55C to +125C
J13-J15 = FPC_22P_0P5_90: CON FPC 22PIN 0.5mm Vertical Type; MFG_NAME01: WENZHANGJIMEI; MFG_PN01: 5001-FCZ0544-22R1-00; Polyhex_Number: PD.010.0159; Temp Range: -20C to +85C; Temp_Range: -20C to +85C
Q11 = 2SK3018_SOT323: NMOS SW 30V 100mA SOT-323; MFG_NAME01: CHANGJING ELECTRONICS; Polyhex_Number: PD.014.0008
R297-R304 R307-R310 R359 R360 R363 R364 R372 R376 R377 R381 R526 R531 = RES: RES MF ZERO OHM 1/16W 5% 0402; AGILE_PN: 470-75394; CAD_APPROVED: Yes; FPLIST: RC0402_25,RC0402_HD,RC0402_X2,0402_CC; HEIGHT: 0.45 MM; MFG_NAME01: YAGEO; MFG_PN01: RC0402JR-070RL; Polyhex_Number: PD.004.0009; ROHS: Yes; Tolerance: 5%; VOLTAGE: 50V
TP82 TP85 TP93 TP98 TP103 TP104 TP106 TP108-TP117 TP124 TP129-TP134 TP145-TP147 = TESTLOOP: TEST POINT PAD 50MIL DIA SMT, NO PART TO ORDER; AGILE_PN: 211-76644; ASSY_OPT: DNP; CAD_APPROVED: Yes; HEIGHT: 0.1MM; MFG_NAME01: NOTACOMPONENT; MFG_PN01: NOTACOMPONENT; Polyhex_Number: TEST POINT; ROHS: Yes
C358 C359 C365 C449-C452 C460 = CAP_NP: CAP CER 0.1UF 16V 10% X5R 0402; CAD_APPROVED: Yes; FPLIST: CC0402_25,CC0402_HD,0402_CC,capc0402_l; HEIGHT: 0.55MM; MFG_NAME01: SAMSUNG; MFG_PN01: CL05B104K05NNNC; Polyhex_Number: PD.005.0036; ROHS: Yes; Tolerance: 10%; VOLTAGE: 16V
C362 C363 = CAP_NP: CAP CER 2.2uF 10V 10% X5R 0402; CAD_APPROVED: Yes; FPLIST: CC0402_25,CC0402_HD,0402_CC,capc0402_l; HEIGHT: 0.55 MM; MFG_NAME01: SAMSUNG; MFG_PN01: CL05A225KO5NQNC; Package Size: 0402; Polyhex_Number: PD.005.0041; ROHS: Yes; Tolerance: 10%; VOLTAGE: 16V
C364 = CAP_NP: CAP CER 1UF 16V 10% X5R 0402; CAD_APPROVED: Yes; FPLIST: CC0402_25,CC0402_HD,0402_CC,capc0402_l; HEIGHT: 0.55MM; MFG_NAME01: SAMSUNG; MFG_PN01: CL05A105KO5NNNC; Polyhex_Number: PD.005.0099; ROHS: Yes; Tolerance: 10%; VOLTAGE: 16V
C366 C368-C370 = CAP_NP: CAP CER 56pF 50V 10% C0G 0402; CAD_APPROVED: Yes; FPLIST: CC0402_25,CC0402_HD,0402_CC,capc0402_l; HEIGHT: 0.55MM; MFG_NAME01: SAMSUNG; MFG_PN01: 0402CG560J500NT; Polyhex_Number: PD.005.0131; ROHS: Yes; Tolerance: 10%; VOLTAGE: 50V
C371 = CAP_NP: CAP CER 47UF 16V 10% X5R 1210; CAD_APPROVED: Yes; HEIGHT: 2.7 mm; MFG_NAME01: SAMSUNG; MFG_PN01: CL32A476KOJNNNE; Polyhex_Number: PD.005.0133; ROHS: Yes; Tolerance: 10%; VOLTAGE: 16V
D17 D19 D21 D23 = DIODE: DIODE SCH 30V 200MA -- SOD323; AGILE_PN: 480-30039; CAD_APPROVED: Yes; HEIGHT: 1.15MM; MFG_NAME01: ON SEMICONDUCTOR; Polyhex_Number: PD.020.0073
D18 = DIODE: DIODE SCH 30V 200MA -- SOD323; AGILE_PN: 480-30039; ASSY_OPT: DNP; CAD_APPROVED: Yes; HEIGHT: 1.15MM; MFG_NAME01: ON SEMICONDUCTOR; Polyhex_Number: PD.020.0073
F4 = PTC: SERIES SURFACE MOUNT PTC 6V 0.5A; MFG_NAME01: JDTfuse; Polyhex_Number: PD.004.0160
J19 = HYTP-SMT1-2151: CON 16PIN USB TYPE C SMT; HEIGHT: 3.16mm; MFG_NAME01: HUAYAO; Polyhex_Number: PD.010.0129; ROHS: YES; Temp Range: -25C to +85C; Temp_Range: -25C to +85C
J20 = CONN_HDR_5X2: HDR 2X5 SMT 50MIL CTR 246H AU; 3D_Mechanical_Footprint_File: ftp://fcl.am.freescale.net/ALLEGRO/step/hdr205_10m_50_sm_k.STEP; AGILE_PN: 211-79478; CAD_APPROVED: Yes; HEIGHT: 6.25MM; MFG_NAME01: CHANGJIANG CONNECTORS; Polyhex_Number: PD.010.0160; ROHS: Yes
L18 = DLW43: IND CHK 51uH@1MHZ 230mA -30%/+50% 1812; MFG_NAME01: MURATA; Polyhex_Number: PD.012.0063
P2 = JST_SH_2P: CON SH 2PIN PITCH 1.0MM VERTICAL SMT; MFG_NAME01: WENZHANGJIMEI; MFG_PN01: 5001-SH0010B-2G1-00; Polyhex_Number: PD.010.0163
R345 R346 R353 R354 = RES: RES MF 22 OHM 1/20W 5% 0201; AGILE_PN: 470-82323; CAD_APPROVED: Yes; FPLIST: RC0201,0201_CC; HEIGHT: 0.26MM; MFG_NAME01: YAGEO; MFG_PN01: RC0201JR-0722RL; Polyhex_Number: PD.004.0173; ROHS: Yes; Temp Range: -55°C ~ 125°C; Temp_Range: -55°C ~ 125°C; Tolerance: 5%; VOLTAGE: 25V
R350 = RES: RES MF 100 OHM 1/16W 5% 0402; AGILE_PN: 470-75394; CAD_APPROVED: Yes; FPLIST: RC0402_25,RC0402_HD,RC0402_X2,0402_CC; HEIGHT: 0.45 MM; MFG_NAME01: YAGEO; MFG_PN01: RC0402JR-07100RL; Polyhex_Number: PD.004.0012; ROHS: Yes; Tolerance: 5%; VOLTAGE: 50V
R351 R352 = RES: RES MF 5K1 1/16W 1% 0402; AGILE_PN: 470-82323; CAD_APPROVED: Yes; FPLIST: RC0201,0201_CC; HEIGHT: 0.26MM; MFG_NAME01: YAGEO; MFG_PN01: RC0402FR-075K1L; Polyhex_Number: PD.004.0039; ROHS: Yes; Temp Range: -55°C ~ 125°C; Temp_Range: -55°C ~ 125°C; Tolerance: 1%; VOLTAGE: 50V
R355 R367 R519 R520 = RES: RES MF ZERO OHM 1/20W 5% 0201; AGILE_PN: 470-82323; CAD_APPROVED: Yes; FPLIST: RC0201,0201_CC; HEIGHT: 0.26MM; MFG_NAME01: YAGEO; MFG_PN01: RC0201JR-070RL; Polyhex_Number: PD.004.0171; ROHS: Yes; Temp Range: -55°C ~ 125°C; Temp_Range: -55°C ~ 125°C; Tolerance: 5%; VOLTAGE: 25V
R356 R515 R516 R555 = RES: RES MF ZERO OHM 1/20W 5% 0201; AGILE_PN: 470-82323; ASSY_OPT: DNP; CAD_APPROVED: Yes; FPLIST: RC0201,0201_CC; HEIGHT: 0.26MM; MFG_NAME01: YAGEO; MFG_PN01: RC0201JR-070RL; Polyhex_Number: PD.004.0171; ROHS: Yes; Temp Range: -55°C ~ 125°C; Temp_Range: -55°C ~ 125°C; Tolerance: 5%; VOLTAGE: 25V
R357 = RES: RES MF 2K2 1/16W 5% 0402; ASSY_OPT: DNP; CAD_APPROVED: Yes; HEIGHT: 0.23mm; MFG_NAME01: YAGEO; MFG_PN01: RC0402JR-072K2L; Polyhex_Number: PD.004.0098; ROHS: Yes; Tolerance: 5%; VOLTAGE: 50V
R358 = RES: RES MF 100K 1/16W 5% 0402; AGILE_PN: 470-75597; CAD_APPROVED: Yes; FPLIST: RC0402_25,RC0402_HD,0402_CC; HEIGHT: 0.40 MM; MFG_NAME01: YAGEO; MFG_PN01: RC0402JR-07100KL; Polyhex_Number: PD.004.0004; ROHS: Yes; Temp Range: -55C to +155C; Temp_Range: -55C to +155C; Tolerance: 5%; VOLTAGE: 50V
R361 R368 R525 = RES: RES MF 60R4 1/10W 1% 0603; AGILE_PN: 470-75394; CAD_APPROVED: Yes; HEIGHT: 0.45 MM; MFG_NAME01: YAGEO; MFG_PN01: RC0603FR-0760R4L; Polyhex_Number: PD.004.0049; ROHS: Yes; Tolerance: 1%; VOLTAGE: 75V
R362 R366 R380 R507 R508 R537 = RES: RES MF ZERO OHM 1/16W 5% 0402; AGILE_PN: 470-75394; ASSY_OPT: DNP; CAD_APPROVED: Yes; FPLIST: RC0402_25,RC0402_HD,RC0402_X2,0402_CC; HEIGHT: 0.45 MM; MFG_NAME01: YAGEO; MFG_PN01: RC0402JR-070RL; Polyhex_Number: PD.004.0009; ROHS: Yes; Tolerance: 5%; VOLTAGE: 50V
R369 R374 = RES: RES MF 10K 1/16W 5% 0402; AGILE_PN: 470-75557; ASSY_OPT: DNP; CAD_APPROVED: Yes; FPLIST: RC0402_25,RC0402_HD,0402_CC; HEIGHT: 0.4 MM; MFG_NAME01: YAGEO; MFG_PN01: RC0402JR-0710KL; Polyhex_Number: PD.004.0010; ROHS: Yes; Tolerance: 5%; VOLTAGE: 50V
R370 = RES: RES MF 330R 1/16W 5% 0402; CAD_APPROVED: Yes; HEIGHT: 0.4 MM; MFG_NAME01: YAGEO; MFG_PN01: RC0402JR-07330RL; Polyhex_Number: PD.004.0034; ROHS: Yes; Tolerance: 5%; VOLTAGE: 50V
R371 R522 R523 R527 = RES: RES MF 1K 1/16W 5% 0402; CAD_APPROVED: Yes; HEIGHT: 0.4 MM; MFG_NAME01: YAGEO; MFG_PN01: RC0402JR-071KL; Polyhex_Number: PD.004.0007; ROHS: Yes; Tolerance: 5%
R373 R378 R379 R532 R533 = RES: RES MF 10K 1/20W 5% 0201; CAD_APPROVED: Yes; HEIGHT: 0.23mm; MFG_NAME01: YAGEO; MFG_PN01: RC0201JR-0710KL; Polyhex_Number: PD.004.0069; ROHS: Yes; Tolerance: 5%; VOLTAGE: 25V
SW9 = SW_1P27_1P: SW 1P SPST DIP 25MA 24V SMT; HEIGHT: 2.3mm; MFG_NAME01: JINRUN; Polyhex_Number: PD.010.0165
TVS6 = SM712: TVS SM712 12V/7V SOT-23; MFG_NAME01: MSKSEMI; Polyhex_Number: PD.020.0072
U48 = CH342F: USB TO DUAL SERIAL CHIP; MFG_NAME01: WCH; Polyhex_Number: PD.008.0324; Temp Range: -40C to +85C; Temp_Range: -40C to +85C
U49 = PESD1USB30_5P: IC EMI FILTER ESD PROTECTION 15kV/LINE WLCSP5; 3D_Mechanical_Footprint_File: http://fcl.am.freescale.net/ALLEGRO/step/wlcsp5_0p4_0p82x1p22.STEP; AGILE_PN: 315-84061; CAD_APPROVED: Yes; HEIGHT: 0.6MM; MFG_NAME01: NEXPERIA; Polyhex_Number: PD.008.0311; ROHS: Yes
U50 = LDO_SOT23_5: IC, ME6211C18M5G, 1.8V, LDO, microne; MFG_NAME01: microne; Polyhex_Number: PD.008.0050
U51 = TJA1051T_3: TJA1051T/3/2Z,SO8; MFG_NAME01: NXP SEMICONDUCTORS; Polyhex_Number: PD.008.0325
U52 = PCF2131_4: PCF2131TF,HLSON16,Nano-power highly accurate RTC with integrated quartz crystal; CAD_APPROVED: Yes; HEIGHT: 1.75MM; MFG_NAME01: NXP SEMICONDUCTORS; Polyhex_Number: PD.008.0326; ROHS: Yes
BH1 = MOUNT_HOLE: FASTENER STANDOFF M2 Length-5.0mm; AGILE_PN: 280-77165; CAD_APPROVED: Yes; HEIGHT: 5.0MM; MFG_NAME01: SINHOOST; Polyhex_Number: PD.019.0017; ROHS: Yes
C454 C455 C457 = CAP_NP: CAP CER 100uF 16V 20% X5R 1210; AGILE_PN: 150-79142; CAD_APPROVED: Yes; FPLIST: CC1210,1210_CC; HEIGHT: 2.8MM; MFG_NAME01: TAIYO YUDEN; MFG_PN01: EMK325ABJ107MM-T; Package Size: 1210; Polyhex_Number: PD.005.0132; ROHS: Yes; Tolerance: 20%; VOLTAGE: 16V
C456 = CAP_NP: CAP CER 100uF 16V 20% X5R 1210; AGILE_PN: 150-79142; ASSY_OPT: DNP; CAD_APPROVED: Yes; FPLIST: CC1210,1210_CC; HEIGHT: 2.8MM; MFG_NAME01: TAIYO YUDEN; MFG_PN01: EMK325ABJ107MM-T; Package Size: 1210; Polyhex_Number: PD.005.0132; ROHS: Yes; Tolerance: 20%; VOLTAGE: 16V
C458 = CAP_NP: CAP CER 0.22uF 16V 10% X5R 0402; AGILE_PN: 150-79999; CAD_APPROVED: Yes; FPLIST: CC0402_25,CC0402_HD,0402_CC; HEIGHT: 0.55MM; MFG_NAME01: SAMSUNG; MFG_PN01: CL05B224KO5NNNC; Package Size: 0402; Polyhex_Number: PD.005.0050; ROHS: Yes; Temp Range: -55°C to +85°C; Temp_Range: -55°C to +85°C; Tolerance: 10%; VOLTAGE: 16V
C459 = CAP_NP: CAP CER 0.01uF 50V 10% X7R 0402; CAD_APPROVED: Yes; FPLIST: CC0402_25,CC0402_HD,0402_CC,capc0402_l; HEIGHT: 0.55 MM; MFG_NAME01: SAMSUNG; MFG_PN01: CL05B103KB5NNNC; Package Size: 0402; Polyhex_Number: PD.005.0006; ROHS: Yes; Tolerance: 10%; VOLTAGE: 50V
D22 = LED: LED GRN SGL 25MA SMT 0603; AGILE_PN: 370-76672; CAD_APPROVED: Yes; HEIGHT: 0.8 MM; MFG_NAME01: HONGQI; MFG_PN01: HQ19-2132SYGC; Polyhex_Number: PD.020.0041; ROHS: Yes; VOLTAGE: 2V
D24 = LED: LED BLUE SGL 20MA 0603; AGILE_PN: 370-76572; CAD_APPROVED: Yes; HEIGHT: 0.28MM; MFG_NAME01: NATIONSTAR; MFG_PN01: NCD0603B3; Polyhex_Number: PD.020.0014; ROHS: Yes; Rated Voltage: 2V; Temp Range: -40°C to +85°C; Temp_Range: -40°C to +85°C; VOLTAGE: 2v
J24 = CON_67_FEMALE_RA_A: 0.5MM PITCH M.2 H6.7 KEY E; AGILE_PN: 211-80089; CAD_APPROVED: Yes; HEIGHT: 6.7MM; MFG_NAME01: LOTES; MFG_PN01: APCI0154-P001A; Polyhex_Number: PD.010.0162; ROHS: Yes; Temp Range: -40°C to 80°C; Temp_Range: -40°C to 80°C
Q17 = PMOS_NCE30P28Q: PMOS NCE30P28Q Vds=-30V Vgs=+/-20V, Id=-28A, QFN_3x3-8L, ncepower; MFG_NAME01: NCEPOWER; Polyhex_Number: PD.014.0020
Q18 Q19 = NX3008NBKW_SOT323: TRAN NMOS SW 30V 350mA AEC-Q101 SC-70; AGILE_PN: 480-79736; CAD_APPROVED: Yes; HEIGHT: 1.1MM; MFG_NAME01: NEXPERIA; Polyhex_Number: PD.014.0033; ROHS: Yes
R524 = RES: RES MF 22K 1/16W 5% 0402; AGILE_PN: 470-75609; CAD_APPROVED: Yes; FPLIST: RC0402_25,RC0402_HD,0402_CC; HEIGHT: 0.41mm; MFG_NAME01: YAGEO; MFG_PN01: RC0402JR-0722KL; Polyhex_Number: PD.004.0103; ROHS: Yes; Tolerance: 5%; VOLTAGE: 50V
R528 = RES: RES MF 1K 1/16W 5% 0402; ASSY_OPT: DNP; CAD_APPROVED: Yes; HEIGHT: 0.4 MM; MFG_NAME01: YAGEO; MFG_PN01: RC0402JR-071KL; Polyhex_Number: PD.004.0007; ROHS: Yes; Tolerance: 5%
R529 = RES: RES MF 1M 1/16W 1% 0402; AGILE_PN: 470-80575; CAD_APPROVED: Yes; FPLIST: RC0402_25,RC0402_HD,0402_CC; HEIGHT: 0.4MM; MFG_NAME01: YAGEO; MFG_PN01: RC0402FR-071ML; Polyhex_Number: PD.004.0230; ROHS: Yes; Tolerance: 1%
C465 C466 C471 C472 = CAP_NP: CAP CER 22uF 10V 20% X5R 0603; AGILE_PN: 150-79530; CAD_APPROVED: Yes; FPLIST: CC0603_OV,CC0603,0603_CC; HEIGHT: 1MM; MFG_NAME01: SAMSUNG; MFG_PN01: CL10A226MP8NUNE; Package Size: 0603; Polyhex_Number: PD.005.0003; ROHS: Yes; SIGNAL_MODEL: DEFAULT_CAPACITOR_2.2e+07pF_2_1; Tolerance: 20%; VOLTAGE: 10V; WVDC: 6.3V
J25 J26 = IPEX_4: CON RF 4ST COAXIAL CONNECTOR; ASSY_OPT: DNP; MFG_NAME01: HUAXINR; Polyhex_Number: PD.010.0087
R534 R535 = RES: RES MF 51K 1/16W 5% 0402; ASSY_OPT: DNP; CAD_APPROVED: Yes; HEIGHT: 0.23mm; MFG_NAME01: YAGEO; MFG_PN01: RC0402FR-0751KL; Polyhex_Number: PD.004.0184; ROHS: Yes; Tolerance: 5%; VOLTAGE: 50V
U64 = MAYA-W27x: MAYA-W276-00B,LGA86,10.4*14.3*2.0mm,0-70+C(SDIO,UART,SPI); MFG_NAME01: Ublox; Polyhex_Number: PD.017.0026

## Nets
GND: BH1.1 C110.2 C111.2 C112.2 C113.2 C114.2 C115.2 C116.2 C117.2 C118.2 C119.2 C120.2 C331.2 C332.2 C333.2 C334.2 C335.2 C336.2 C337.2 C358.2 C359.2 C360.2 C361.2 C362.2 C363.2 C364.2 C365.2 C366.2 C367.2 C368.2 C369.2 C370.2 C371.2 C372.2 C373.2 C374.2 C449.2 C450.2 C451.2 C452.2 C453.2 C454.2 C455.2 C456.2 C457.2 C460.2 C461.2 C462.2 C463.2 C464.2 C465.2 C466.2 C467.2 C468.2 C469.2 C470.2 C471.2 C472.2 C473.2 C474.2 C475.2 C476.2 J13.1 J13.4 J13.7 J13.10 J13.13 J13.16 J13.19 J13.23 J13.24 J14.1 J14.4 J14.7 J14.10 J14.13 J14.16 J14.19 J14.23 J14.24 J15.1 J15.4 J15.7 J15.10 J15.13 J15.16 J15.19 J15.23 J15.24 J19.1(SH1) J19.2(SH2) J19.3(SH3) J19.4(SH4) J19.A1B12(AGND) J19.B1A12(BGND) J20.3(A2) J20.5(A3) J24.1(GND1) J24.7(GND2) J24.18(GND3) J24.33(GND5) J24.39(GND4) J24.45(GND6) J24.51(GND7) J24.57(GND8) J24.63(GND9) J24.69(GND10) J24.75(GND11) J25.2 J25.3 J25.4 J26.2 J26.3 J26.4 P2.2 Q18.2(SOURCE) Q19.2(SOURCE) R351.2 R352.2 R355.2 R356.2 R369.2 R378.2 R379.2 R529.2 R534.2 R535.2 TP82.1(Pin1) TP85.1(Pin1) TP93.1(Pin1) TP98.1(Pin1) TP103.1(Pin1) TP108.1(Pin1) TP117.1(Pin1) TP124.1(Pin1) TP129.1(Pin1) TVS6.3 U3.A6(VSS1) U3.C4(VSSQ1) U3.E7(VSS2) U3.G5(VSS3) U3.H10(VSS4) U3.J5(VSS5) U3.K8(VSS6) U3.N2(VSSQ2) U3.N5(VSSQ3) U3.P4(VSSQ4) U3.P6(VSSQ5) U4.4(VSS) U4.9(EP) U48.2(GND) U48.25(EPAD) U49.B1(GND) U50.2(GND) U51.2(GND) U52.7(VSS) U52.17(GND) U64.A1(GND20) U64.A9(GND21) U64.B2(GND18) U64.B8(GND19) U64.E4(GND16) U64.E5(GND17) U64.F4(GND14) U64.F5(GND15) U64.H4(GND12) U64.H5(GND13) U64.K2(GND6) U64.K3(GND7) U64.K4(GND8) U64.K6(GND9) U64.K7(GND10) U64.K8(GND11) U64.L1(GND5) U64.M1(GND1) U64.M2(GND2) U64.M8(GND3) U64.M9(GND4) ; also on sheet 4 5 7 8 9 10 11 12 13 14 15 16 17 18 19 20 26 27
VCC_EXT_1V8: FB16.1 ; also on sheet 11 20
VCC_EXT_3V3: C331.1 C457.1 C458.1 FB15.1 FB19.1 Q17.1(SOURCE1) Q17.2(SOURCE2) Q17.3(SOURCE3) R360.1 R524.1 R528.1 ; also on sheet 11 19 20 27
VDD1V8_DBG: C363.1 U48.5(VIO) U50.5(OUT)
VDD3V3_DBG: C358.1 C361.1 C362.1 R358.1 U48.6(V3) U50.1(IN)
VDD5V_DBG: C359.1 C360.1 F4.2 U48.7(VDD5) U48.8(VBUS)
VDD_1V8: C113.1 C114.1 C115.1 C116.1 C119.1 C120.1 C469.1 C470.1 C475.1 C476.1 D17.A Q11.1(GATE) R36.1 R37.1 R38.1 R305.1 R347.1 R348.1 R350.1 R357.1 R374.1 R532.1 R533.1 R555.1 TP147.1(Pin1) U3.C6(VCCQ1) U3.M4(VCCQ2) U3.N4(VCCQ3) U3.P3(VCCQ4) U3.P5(VCCQ5) U4.8(VCC) U64.A6(VIO_SD) U64.A8(VIO) ; also on sheet 4 5 6 9 10 12 16 18 26 27
VDD_3V3: C110.1 C111.1 C112.1 R375.1 U3.E6(VCC1) U3.F5(VCC2) U3.J10(VCC3) U3.K9(VCC4) ; also on sheet 4 10 11 12 13 14 15 16 17 18 20 26 27
VDD_5V: R359.1 ; also on sheet 11 12 13 18 19 20 27
VDD_COIN_3V: P2.1 R371.2 R372.1 TP148.1(Pin1)
CAM1_GPIO: J14.17 R299.2 TP110.1(Pin1)
CAM1_MCLK: J14.18 R301.2 TP112.1(Pin1)
CAM1_SCL: J14.20 R303.2 TP114.1(Pin1)
CAM1_SDA: J14.21 R304.2 TP115.1(Pin1)
CAM2_GPIO: J13.17 R297.2 TP104.1(Pin1)
CAM2_MCLK: J13.18 R298.2 TP106.1(Pin1)
CAM2_SCL: J13.20 R300.2 TP109.1(Pin1)
CAM2_SDA: J13.21 R302.2 TP111.1(Pin1)
CAN1_RX_3V3: R364.2 ; also on sheet 26
CAN1_TX_3V3: R363.1 ; also on sheet 26
CAN-RXD: R364.1 U51.4(RXD)
CAN-TXD: R363.2 U51.1(TXD)
CAN_H: C366.1 L18.2 R361.2 R362.2 TVS6.1 ; also on sheet 27
CAN_L: C370.1 L18.3 R366.2 R368.2 TVS6.2 ; also on sheet 27
CAN_STBY: R367.1 ; also on sheet 26
CAN_VDD_5V: C364.1 C365.1 R359.2 U51.3(VCC)
CAN_VIO_3V3: C367.1 R360.2 R365.1 U51.5(VIO)
CANH: L18.1 R362.1 U51.7(CANH)
CANL: L18.4 R366.1 U51.6(CANL)
CSI1_CKN: J14.8 TP95.1(Pin1) ; also on sheet 7
CSI1_CKP: J14.9 TP97.1(Pin1) ; also on sheet 7
CSI1_DN0: J14.2 TP81.1(Pin1) ; also on sheet 7
CSI1_DN1: J14.5 TP90.1(Pin1) ; also on sheet 7
CSI1_DN2: J14.11 TP100.1(Pin1) ; also on sheet 7
CSI1_DN3: J14.14 TP105.1(Pin1) ; also on sheet 7
CSI1_DP0: J14.3 TP88.1(Pin1) ; also on sheet 7
CSI1_DP1: J14.6 TP92.1(Pin1) ; also on sheet 7
CSI1_DP2: J14.12 TP102.1(Pin1) ; also on sheet 7
CSI1_DP3: J14.15 TP107.1(Pin1) ; also on sheet 7
CSI1_nRST: R299.1 ; also on sheet 26
CSI2_CKN: J13.8 TP89.1(Pin1) ; also on sheet 7
CSI2_CKP: J13.9 TP91.1(Pin1) ; also on sheet 7
CSI2_DN0: J13.2 TP83.1(Pin1) ; also on sheet 7
CSI2_DN1: J13.5 TP86.1(Pin1) ; also on sheet 7
CSI2_DN2: J13.11 TP94.1(Pin1) ; also on sheet 7
CSI2_DN3: J13.14 TP99.1(Pin1) ; also on sheet 7
CSI2_DP0: J13.3 TP84.1(Pin1) ; also on sheet 7
CSI2_DP1: J13.6 TP87.1(Pin1) ; also on sheet 7
CSI2_DP2: J13.12 TP96.1(Pin1) ; also on sheet 7
CSI2_DP3: J13.15 TP101.1(Pin1) ; also on sheet 7
CSI2_nRST: R297.1 ; also on sheet 26
CSI_MCLK: R298.1 R301.1 ; also on sheet 6
DBG_USB_DN: J19.A7(ADN1) J19.B7(BDN1) U49.A1(CH1_IN+)
DBG_USB_DP: J19.A6(ADP1) J19.B6(BDP1) U49.A2(CH1_IN-)
DEB_UART2_RX: R345.1 U48.21(TXD0)
DEB_UART2_TX: R346.2 U48.20(RXD0)
DEB_UART4_RX: R354.1 U48.13(TXD1)
DEB_UART4_TX: R353.2 U48.12(RXD1)
DEBUG_USB_DN: U48.4(UD-) U49.C1(CH1_OUT+)
DEBUG_USB_DP: U48.3(UD+) U49.C2(CH1_OUT-)
DSI&CAM_3V3: C332.1 C333.1 C334.1 C335.1 C336.1 C337.1 FB19.2 J13.22 J14.22 J15.22 R306.1 TP113.1(Pin1) TP116.1(Pin1) TP134.1(Pin1)
DSI_CKN: J15.8 TP122.1(Pin1) ; also on sheet 7
DSI_CKP: J15.9 TP123.1(Pin1) ; also on sheet 7
DSI_CTP_nINT: Q11.2(SOURCE) R305.2 ; also on sheet 6
DSI_CTP_nINT_3V3: Q11.3(DRAIN) R306.2 R307.1
DSI_CTP_RST: R308.1 ; also on sheet 26
DSI_DN0: J15.2 TP118.1(Pin1) ; also on sheet 7
DSI_DN1: J15.5 TP120.1(Pin1) ; also on sheet 7
DSI_DN2: J15.11 TP125.1(Pin1) ; also on sheet 7
DSI_DN3: J15.14 TP127.1(Pin1) ; also on sheet 7
DSI_DP0: J15.3 TP119.1(Pin1) ; also on sheet 7
DSI_DP1: J15.6 TP121.1(Pin1) ; also on sheet 7
DSI_DP2: J15.12 TP126.1(Pin1) ; also on sheet 7
DSI_DP3: J15.15 TP128.1(Pin1) ; also on sheet 7
DSI_SCL: J15.20 R309.2 TP132.1(Pin1)
DSI_SDA: J15.21 R310.2 TP133.1(Pin1)
eMMC_VDDIM: C117.1 C118.1 U3.C2(VDDI)
I2C2_SCL: R519.1 ; also on sheet 6 26
I2C2_SCL_3V3: R303.1 R309.1 R377.1 ; also on sheet 20 26
I2C2_SDA: R520.1 ; also on sheet 6 26
I2C2_SDA_3V3: R304.1 R310.1 R376.1 ; also on sheet 20 26
I2C3_SCL_3V3: R300.1 ; also on sheet 20 26 27
I2C3_SDA_3V3: R302.1 ; also on sheet 20 26 27
JTAG_MOD: R357.2 TP146.1(Pin1) ; also on sheet 8
JTAG_RESET: D18.C(K) D19.C(K) J20.10(B5) R349.2
JTAG_TCK: J20.4(B2) ; also on sheet 8
JTAG_TDI: J20.8(B4) R348.2 ; also on sheet 8
JTAG_TDO: J20.6(B3) ; also on sheet 8
JTAG_TMS: J20.2(B1) R347.2 ; also on sheet 8
KEYE_PCIe_nCLKREQ: J24.53(~{CLKREQ0}) ; also on sheet 26
KEYE_PCIe_nDIS1: J24.56(~{W_DISABLE1}) R527.1 ; also on sheet 26
KEYE_PCIe_nDIS2: J24.54(~{W_DISABLE2}) TP163.1(Pin1) ; also on sheet 26
KEYE_PCIe_nRST: R515.1 ; also on sheet 26
KEYE_PCIe_nWAKE: J24.55(~{PEWAKE0}) ; also on sheet 26
KEYE_PCIE_RXN: J24.43(PER_N0) ; also on sheet 26
KEYE_PCIE_RXP: J24.41(PER_P0) ; also on sheet 26
KEYE_PCIE_TXN: J24.37(PET_N0) ; also on sheet 26
KEYE_PCIE_TXP: J24.35(PET_P0) ; also on sheet 26
KEYE_REF_CLK_32K: R516.1 ; also on sheet 26
KEYE_REF_CLKN: J24.49(REFCLK_N0) ; also on sheet 26
KEYE_REF_CLKP: J24.47(REFCLK_P0) ; also on sheet 26
KEYE_VDD3V3: C449.1 C450.1 C451.1 C452.1 C453.1 C454.1 C455.1 C456.1 C459.1 J24.2(3V3_1) J24.4(3V3_2) J24.72(3V3_3) J24.74(3V3_4) Q17.5(DRAIN5) Q17.6(DRAIN6) Q17.7(DRAIN7) Q17.8(DRAIN8) R521.1 R522.1 R523.1 R525.1
M2_BT_WAKE: D23.C(K) J24.20(~{UART_WAKE}) R521.2
M2_BT_WAKE_HOST: D23.A ; also on sheet 26
M2_ECSPI2_MISO: J24.40(VEN_DEF2) ; also on sheet 26
M2_ECSPI2_MOSI: J24.38(VEN_DEF1) ; also on sheet 26
M2_ECSPI2_SCLK: J24.42(VEN_DEF3) ; also on sheet 26
M2_ECSPI2_SS0: J24.64(RESERVED) R555.2 ; also on sheet 26
M2_I2C_SCL: J24.60(I2C_CLK) R519.2
M2_I2C_SDA: J24.58(I2C_DATA) R520.2
M2_LED1#: D22.C(CATHODE) J24.6(~{LED1})
M2_LED2#: D24.C(CATHODE) J24.16(~{LED2})
M2_nALERT: J24.62(~{ALERT}) ; also on sheet 26
M2_PCM_CLK: J24.8(I2S_SCK) ; also on sheet 26
M2_PCM_IN: J24.12(I2S_SD_IN) ; also on sheet 26
M2_PCM_OUT: J24.14(I2S_SD_OUT) ; also on sheet 26
M2_PCM_SYNC: J24.10(I2S_WS) ; also on sheet 26
M2_PERST: J24.52(~{PERST0}) R515.2
M2_SD_CLK: J24.9(SDIO_CLK) ; also on sheet 26
M2_SD_CMD: J24.11(SDIO_CMD) ; also on sheet 26
M2_SD_DATA0: J24.13(SDIO_DATA0) ; also on sheet 26
M2_SD_DATA1: J24.15(SDIO_DATA1) ; also on sheet 26
M2_SD_DATA2: J24.17(SDIO_DATA2) ; also on sheet 26
M2_SD_DATA3: J24.19(SDIO_DATA3) ; also on sheet 26
M2_SD_nRST: J24.23(~{SDIO_RST}) ; also on sheet 26
M2_SD_WAKE_HOST: J24.21(~{SDIO_WAKE}) ; also on sheet 26
M2_UART_CTS: J24.36(UART_RTS) ; also on sheet 26
M2_UART_RTS: J24.34(UART_CTS) ; also on sheet 26
M2_UART_RXD: J24.22(UART_RXD) ; also on sheet 26
M2_UART_TXD: J24.32(UART_TXD) ; also on sheet 26
M2_USB_DN: J24.5(USB_D-) R508.2 TP162.1(Pin1)
M2_USB_DP: J24.3(USB_D+) R507.2 TP161.1(Pin1)
PCF2131_SCL: R377.2 U52.2(SCL)
PCF2131_SDA: R376.2 U52.5(SDA/~{CE})
POR_B: D18.A ; also on sheet 8 10 26
QSPIA_DATA0: TP20.1(Pin1) U4.5(DQ0) ; also on sheet 6
QSPIA_DATA1: U4.2(DQ1) ; also on sheet 6
QSPIA_DATA2: U4.3(~{W}/DQ2) ; also on sheet 6
QSPIA_DATA3: U4.7(~{HOLD}/DQ3) ; also on sheet 6
QSPIA_nSS0: R38.2 U4.1(~{S}) ; also on sheet 6
QSPIA_SCLK: TP21.1(Pin1) U4.6(C) ; also on sheet 6
RTC_CLK: TP149.1(Pin1) U52.6(CLKOUT)
RTC_nINTA: R375.2 R381.2 U52.13(~{INTA}) ; also on sheet 26
SD3_CLK: TP18.1(Pin1) U3.M6(CLK) ; also on sheet 6
SD3_CMD: R37.2 TP17.1(Pin1) U3.M5(CMD) ; also on sheet 6
SD3_DATA0: R36.2 TP15.1(Pin1) U3.A3(DAT0) ; also on sheet 6
SD3_DATA1: U3.A4(DAT1) ; also on sheet 6
SD3_DATA2: U3.A5(DAT2) ; also on sheet 6
SD3_DATA3: U3.B2(DAT3) ; also on sheet 6
SD3_DATA4: U3.B3(DAT4) ; also on sheet 6
SD3_DATA5: U3.B4(DAT5) ; also on sheet 6
SD3_DATA6: U3.B5(DAT6) ; also on sheet 6
SD3_DATA7: U3.B6(DAT7) ; also on sheet 6
SD3_STROBE: TP16.1(Pin1) U3.H5(RCLK) ; also on sheet 6
SUSCLK_3V3: J24.50(SUSCLK) R516.2
SYS_nRST: D19.A R380.2 ; also on sheet 10 27
UART2_RXD: R345.2 ; also on sheet 6
UART2_TXD: R346.1 ; also on sheet 6
UART4_RXD: R354.2 ; also on sheet 6
UART4_TXD: R353.1 ; also on sheet 6
USB2_DN: R508.1 ; also on sheet 7 14
USB2_DP: R507.1 ; also on sheet 7 14
VBBS: C374.1 U52.14(BBS)
VLDO_3V3: D21.A R370.1 R373.1 ; also on sheet 12 13
VTREF: J20.1(A1) R350.2
W2_BT_RST: U64.J7(BT_15.4_RST) ; also on sheet 26
W2_BT_WAKE_HOST: U64.E7(BT_15.4_WAKE_HOST) ; also on sheet 26
W2_CONFIG0: R533.2 R534.1 U64.D3(CONFIG0)
W2_CONFIG1: R532.2 R535.1 U64.E3(CONFIG1)
W2_ECSPI2_MISO: U64.F2(SPI_TX/EXT_PRI) ; also on sheet 26
W2_ECSPI2_MOSI: U64.G2(SPI_RX/EXT_GNT) ; also on sheet 26
W2_ECSPI2_SCLK: U64.E2(SPI_CLK/EXT_STATE) ; also on sheet 26
W2_ECSPI2_SS0: U64.C2(SPI_FRM/EXT_REQ) ; also on sheet 26
W2_GPIO27: TP175.1(Pin1) U64.B1(GPIO27)
W2_HOST_WAKE_BT: U64.J9(BT_15.4_DEV_WAKE) ; also on sheet 26
W2_HOST_WAKE_SD: U64.J8(WL_DEV_WAKE) ; also on sheet 26
W2_JTAG_TCK: TP170.1(Pin1) U64.J4(JTAG_TCK)
W2_JTAG_TDI: TP173.1(Pin1) U64.G7(JTAG_TDI)
W2_JTAG_TDO: TP174.1(Pin1) U64.G5(JTAG_TDO)
W2_JTAG_TMS: TP172.1(Pin1) U64.J5(JTAG_TMS)
W2_PCM_CLK: U64.D8(PCM_CLK/I2S_BLCK) ; also on sheet 26
W2_PCM_IN: U64.F9(PCM_DOUT/I2S_DOUT) ; also on sheet 26
W2_PCM_MCLK: TP171.1(Pin1) U64.E8(PCM_MCLK/I2S_CCLK)
W2_PCM_OUT: U64.E9(PCM_DIN/I2S_DIN) ; also on sheet 26
W2_PCM_SYNC: U64.F8(PCM_SYNC/I2S_LRCLK) ; also on sheet 26
W2_PDN: U64.J3(PDn) ; also on sheet 26
W2_RST_IND: U64.C8(RST_IND) ; also on sheet 26
W2_SD_CLK: U64.A4(SD_CLK) ; also on sheet 26
W2_SD_CMD: U64.B4(SD_CMD) ; also on sheet 26
W2_SD_DATA0: U64.B3(SD_DAT0) ; also on sheet 26
W2_SD_DATA1: U64.A3(SD_DAT1) ; also on sheet 26
W2_SD_DATA2: U64.B5(SD_DAT2) ; also on sheet 26
W2_SD_DATA3: U64.A5(SD_DAT3) ; also on sheet 26
W2_SD_nINT: TP164.1(Pin1) U64.D7(SD_INT)
W2_SD_nRST: U64.H7(WL_RST) ; also on sheet 26
W2_SD_WAKE_HOST: U64.F7(WL_WAKE_HOST) ; also on sheet 26
W2_SPI_nINT: U64.D2(SPI_INT/EXT_FREQ) ; also on sheet 26
W2_UART_CTS: U64.H9(UART_RTS) ; also on sheet 26
W2_UART_RTS: U64.H8(UART_CTS) ; also on sheet 26
W2_UART_RXD: U64.G9(UART_TX) ; also on sheet 26
W2_UART_TXD: U64.G8(UART_RX) ; also on sheet 26
WIFI-BT_1V8: C463.1 C464.1 C465.1 C466.1 C467.1 C468.1 FB16.2 U64.A2(1V8)
WIFI-BT_3V3: C461.1 C462.1 C471.1 C472.1 C473.1 C474.1 FB15.2 U64.A7(3V3_2) U64.B7(3V3_1)
N107222690: TP19.1(Pin1) U3.K5(~{RST})
N110594147: J15.18 R307.2 TP131.1(Pin1)
N110594149: J15.17 R308.2 TP130.1(Pin1)
N110597803: F4.1 J19.A4B9(AVBUS) J19.B4A9(BVBUS) TP145.1(Pin1)
N110597854: J19.B5(BCC1) R351.1
N110597856: J19.A5(ACC1) R352.1
N110600881: R365.2 R367.2 R369.1 U51.8(S)
N110600956: C368.1 R361.1 SW9.2(B1)
N110601085: C369.1 R368.1 SW9.1(A1)
N110602649: R373.2 U52.1(IFS)
N110602703: R378.1 U52.3(SDI)
N110602705: R379.1 U52.4(SDO)
N110602788: TP151.1(Pin1) U52.9(~{TS2})
N110602796: TP150.1(Pin1) U52.8(~{TS1})
N110602810: TP152.1(Pin1) U52.10(~{TS3})
N110602818: TP153.1(Pin1) U52.11(~{TS4})
N110602822: R374.2 R380.1 R381.1 U52.12(~{INTB})
N110603012: C371.1 C372.1 R370.2 U52.15(VDD)
N110603079: C373.1 R372.2 U52.16(VBAT)
N110603139: D21.C(K) R371.1
N110608314: D17.C(K) R349.1
N110608420: J20.7(A4) R356.1
N110608429: J20.9(A5) R355.1
N110618683: C458.2 C459.2 Q17.4(GATE) R524.2 R526.1
N110618699: Q18.1(GATE) Q19.3(DRAIN) R526.2
N110618770: C460.1 Q19.1(GATE) R527.2 R528.2 R529.1
N110618816: Q18.3(DRAIN) R525.2
N110620562: D22.A(ANODE) R522.2
N110620582: D24.A(ANODE) R523.2
N111198501: R358.2 U50.3(EN)
N111494442: J25.1 U64.K1(RF_ANT0)
N111494568: R531.1 R537.1 U64.K9(RF_ANT1)
N111494583: R531.2 U64.L9(AND_FEED)
N111614284: J26.1 R537.2

Not connected (* = marked no-connect by the designer): J19 A8(ASBU1)* B8(BSBU1)* M1* M2*; J24 44(COEX3)* 46(COEX_RXD)* 48(COEX_TXD)* 59(PET_P1)* 61(PET_N1)* 65(PER_P1)* 66(UIM_SWP/~{PERST1})* 67(PER_N1)* 68(UIM_PWR_SNK/~{CLKREQ1})* 70(UIM_PWR_SRC/~{PEWAKE1})* 71(REFCLK_P1)* 73(REFCLK_N1)*; U3 A1(NC)* A2(NC)* A7(NC)* A8(NC)* A9(NC)* A10(NC)* A11(NC)* A12(NC)* A13(NC)* A14(NC)* B1(NC)* B7(NC)* B8(NC)* B9(NC)* B10(NC)* B11(NC)* B12(NC)* B13(NC)* B14(NC)* C1(NC)* C3(NC)* C5(NC)* C7(NC)* C8(NC)* C9(NC)* C10(NC)* C11(NC)* C12(NC)* C13(NC)* C14(NC)* D1(NC)* D2(NC)* D3(NC)* D4(NC)* D12(NC)* D13(NC)* D14(NC)* E1(NC)* E2(NC)* E3(NC)* E5(NC)* E8(NC)* E9(VSF1)* E10(VSF2)* E12(NC)* E13(NC)* E14(NC)* F1(NC)* F2(NC)* F3(NC)* F10(VSF3)* F12(NC)* F13(NC)* F14(NC)* G1(NC)* G2(NC)* G3(NC)* G10(NC)* G12(NC)* G13(NC)* G14(NC)* H1(NC)* H2(NC)* H3(NC)* H12(NC)* H13(NC)* H14(NC)* J1(NC)* J2(NC)* J3(NC)* J12(NC)* J13(NC)* J14(NC)* K1(NC)* K2(NC)* K3(NC)* K6(NC)* K7(NC)* K10(VSF4)* K12(NC)* K13(NC)* K14(NC)* L1(NC)* L2(NC)* L3(NC)* L12(NC)* L13(NC)* L14(NC)* M1(NC)* M2(NC)* M3(NC)* M7(NC)* M8(NC)* M9(NC)* M10(NC)* M11(NC)* M12(NC)* M13(NC)* M14(NC)* N1(NC)* N3(NC)* N6(NC)* N7(NC)* N8(NC)* N9(NC)* N10(NC)* N11(NC)* N12(NC)* N13(NC)* N14(NC)* P1(NC)* P2(NC)* P7(NC)* P8(NC)* P9(NC)* P10(NC)* P11(NC)* P12(NC)* P13(NC)* P14(NC)*; U48 1(DI0)* 9(~{RST})* 10(CTS1)* 11(RTS1)* 14(DSR1)* 15(DTR1/TNOW1)* 16(DCD1)* 17(DI1)* 18(CTS0)* 19(RTS0)* 22(DSR0)* 23(DTR0/TNOW0)* 24(DCD0)*; U50 4(NC)*; U64 B6(WCI-2_SOUT)* B9(NC9)* C1(NC4)* C4(NC5)* C5(NC6)* C6(WCI-2_SIN)* C9(NC8)* D1(NC3)* D9(NC7)* E1(NC2)* F1(NC1)* F3(RF_CNTL3)* G1(NC10)* G3(RF_CNTL4)* G4(RF_CNTL2)* H1(NC15)* H2(NC14)* H3(RF_CNTL0)* J1(NC12)* J2(NC11)* K5(NC13)*

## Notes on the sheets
sheet 21
- Module_SPI_RX,Input
- Module_SPI_TX,Output
- Module_PCM_DIN,Input
- Module_PCM_DOUT,Output
- PDN Input,1-Normal,0-power down, module
- WL_RST Input,soft reset Wi-Fi
- BT_15.4_RST Input,soft reset BT
- RST_IND Output,BT soft reset indicator to Host
- CONFIG[1:0]=11 Wi-Fi/SDIO BT/UART 802.15.4/SPI
sheet 22
- Storage
- eMMC5.1
- # 1.8V(Fixed)
- 32GB
- Alternative Part:
- SDINBDA6-32G-I           Western Digital
- EMMC32G-TB29-PZ90     Kingston
- QSPI Flash
- 256Mbit
sheet 23
- M.2 KEY-E 2230 CN
- NC
- NC
- NC
- 1.8V
- o
- 1.8V
- 1.8V
- i
- 1.8V
- NC
- # Standoff for M.2
- NC
- o
- 3.3V
- 1.8V
- 1.8V
- o
- o
- 1.8V
- i
- 1.8V
- NC
- o
- 1.8V
- NC
- i
- i
- 1.8V
- 1.8V
- NC
- o
- 1.8V
- NC
- i
- 1.8V
- NC
- o
- 2230
- NC
- i
- NC
- NC
- i/o
- i
- NC
- NC
- o
- 3.3V
- KEYE_PCIe_nDIS2,BT_INDEPENDENT_RESET
- i
- 3.3V
- KEYE_PCIe_nDIS1,WIFI&BT_Module_Power-down
- NC
- 1.8V
- NC
- 1.8V
- NC
- 1.8V
- 1.8V
- NC
- NC
- NC
- Enable internal PU of CPU.
- WLAN Status
- BT Status
- M.2 KEY-E PWR
- -  50A Max -
- Rds=10 mOhm
  @ Vgs -4.5V
  @ Id = -20A
  Vgs(th) = -1.7V ~ -2.8V
  Vds(max) = -30V
sheet 24
- Debug
- JTAG Interface
- 1.8V IO
- A53 Debug
- 0.5A
- 1.8V IO
- TCK
- TMS
- M7 Debug
- TDO
- TDI
- Warm Reset, CPU ONLY
- Cold Reset
- Split termination for RC tee filter
- fc=1/[2*pie*(Rt/2)*Csplit]
- CAN
- TDK:B82793S0513N201
  ACT45B-510-2P-TL003
- RSUP and CSUP: An appropriate RC filter needs to be
  added to guarantee the chip will only see <0.35 V/ms ramp
  down rate on supply, even if Vdd_in ramp rate is very high.
- #I2C ADDR: 0b'1010011x
- # Coin Cell charge circuits, ONLY
  DESIGNED FOR RECHARGEABLE
  COINE CELL BATTERY!!!
- # If RTC kept during system OFF,
  Coin Cell P2 need to be installed.
